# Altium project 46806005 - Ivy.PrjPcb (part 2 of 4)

## Sheet 800_Peripherals.SchDoc: Ivy - Verdin Industrial Board Rev 1.1
size Letter; Organization: Toradex Solutions Inc.; Address1: 6415 Northwest Drive; Address2: Mississauga, ON, L4V 1X1; Address3: Canada
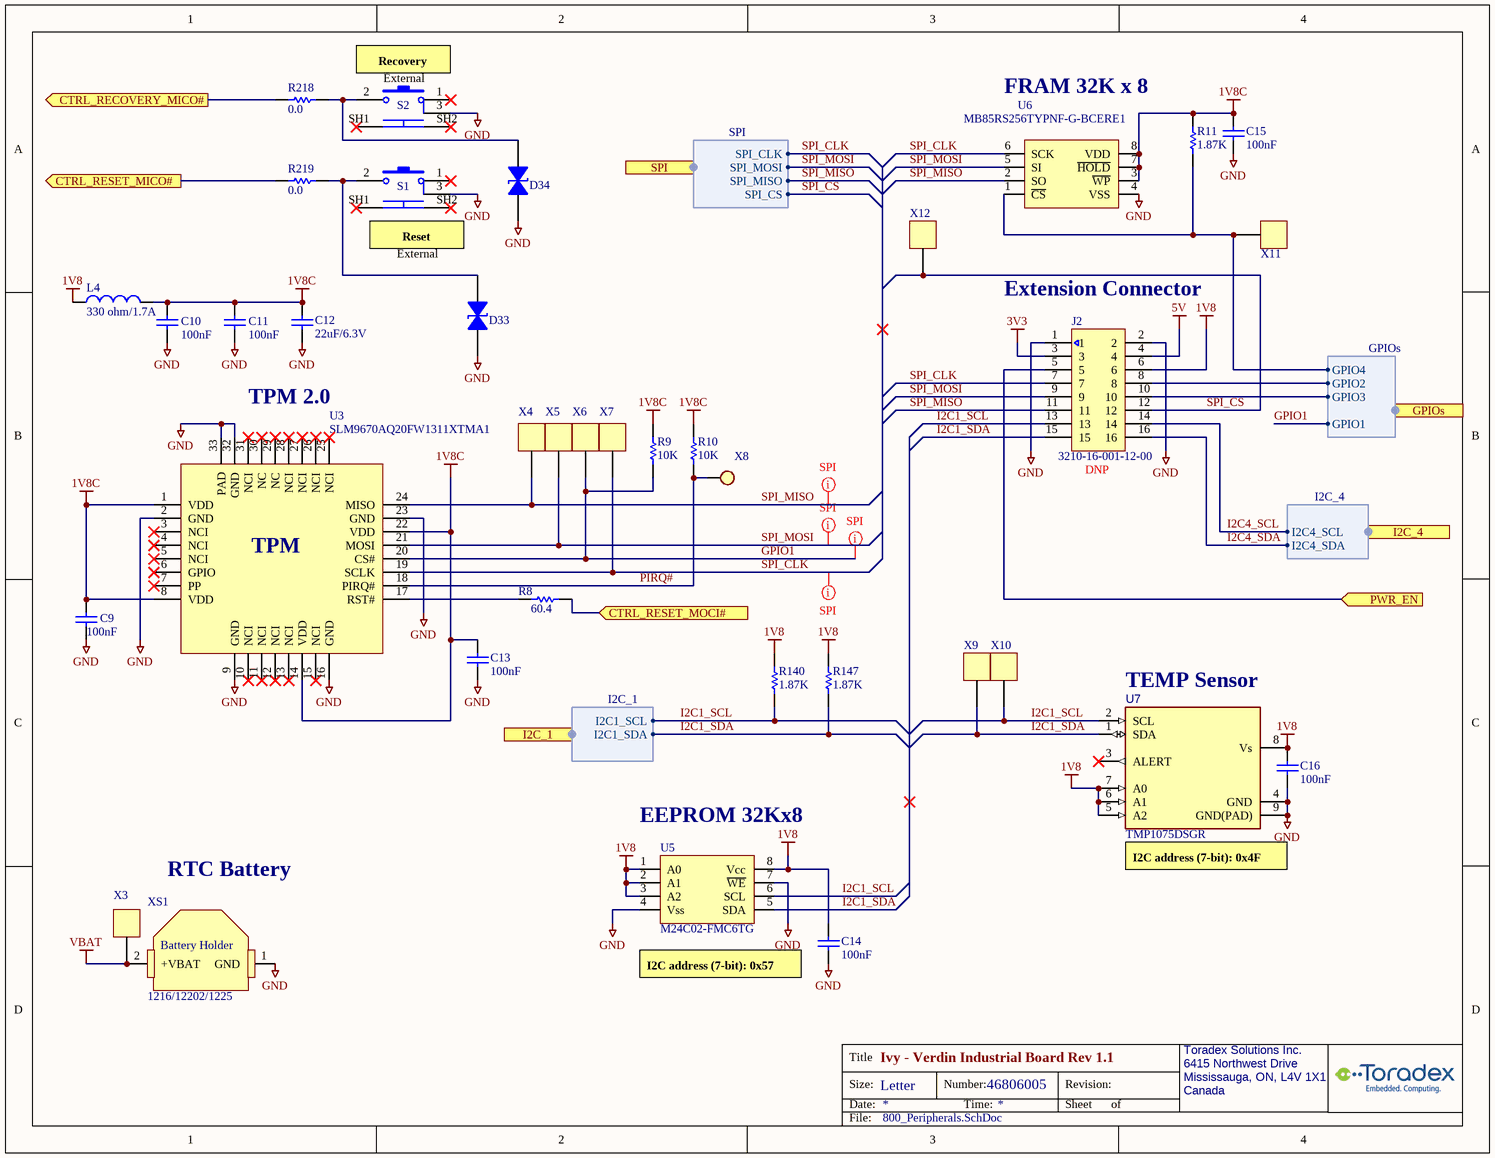
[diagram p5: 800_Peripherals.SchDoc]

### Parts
C9  100nF  [C0402_CAPC1005L]
C10  100nF  [C0402_CAPC1005L]
C11  100nF  [C0402_CAPC1005L]
C12  22uF/6.3V  [C0402_CAPC1005L]
C13  100nF  [C0402_CAPC1005L]
C14  100nF  [C0402_CAPC1005L]
C15  100nF  [C0402_CAPC1005L]
C16  100nF  [C0402_CAPC1005L]
D33  D5V0L1B2S9-7  [SOD923_DIO]  (value not drawn)
D34  D5V0L1B2S9-7  [SOD923_DIO]  (value not drawn)
J2  3210-16-001-12-00  [CNC_CONN16_3210-16-001-12-00]  (no BOM)
L4  value 330 ohm/1.7A  [INDC1608x095]  (hidden comment: 0405-Fer-0603-330ohm/1.7A)
R8  value 60.4  [R/0603]  (hidden comment: 2199-Res-0603-60.4)
R9  value 10K  [R0402_RESC1005L]  (hidden comment: 1572-Res-0402-10K)
R10  value 10K  [R0402_RESC1005L]  (hidden comment: 1572-Res-0402-10K)
R11  value 1.87K  [R0402_RESC1005L]  (hidden comment: 1536-Res-0402-1.87K)
R140  value 1.87K  [R0402_RESC1005L]  (hidden comment: 1536-Res-0402-1.87K)
R147  value 1.87K  [R0402_RESC1005L]  (hidden comment: 1536-Res-0402-1.87K)
R218  value 0.0  [R/0603]  (hidden comment: 0195-Res-0603-0.0ohm)
R219  value 0.0  [R/0603]  (hidden comment: 0195-Res-0603-0.0ohm)
S1  TL3340AF160QG  [SW_TL3340]  (value not drawn)
S2  TL3340AF160QG  [SW_TL3340]  (value not drawn)
U3  SLM9670AQ20FW1311XTMA1  [QFN50P500X500X90-33N-V]
U5  M24C02-FMC6TG  [M24C02FMC6TG]
U6  MB85RS256TYPNF-G-BCERE1  [SOIC-8]
U7  TMP1075DSGR  [WSON-8(2.1x2.1)_PAD]
X3  000-TestPoint  [TestPoint_1]  (value not drawn)
X4  000-TestPoint  [TestPoint_1]  (value not drawn)
X5  000-TestPoint  [TestPoint_1]  (value not drawn)
X6  000-TestPoint  [TestPoint_1]  (value not drawn)
X7  000-TestPoint  [TestPoint_1]  (value not drawn)
X8  000-TestPoint2  [TestPoint_3]  (value not drawn)
X9  000-TestPoint  [TestPoint_1]  (value not drawn)
X10  000-TestPoint  [TestPoint_1]  (value not drawn)
X11  000-TestPoint  [TestPoint_1]  (value not drawn)
X12  000-TestPoint  [TestPoint_1]  (value not drawn)
XS1  1216/12202/1225  [T_KEYSTONE_3000]

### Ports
CTRL_RECOVERY_MICO# (out), CTRL_RESET_MICO# (out), CTRL_RESET_MOCI# (in), GPIOs (harness GPIOs), I2C_1 (harness I2C_1), I2C_4 (harness I2C_4), PWR_EN (in), SPI (harness SPI)

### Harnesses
I2C_1: I2C1_SDA, I2C1_SCL
I2C_4: I2C4_SDA, I2C4_SCL
SPI: SPI_CLK, SPI_MISO, SPI_MOSI, SPI_CS
GPIOs: GPIO4, GPIO2, GPIO3, GPIO1

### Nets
1V8: C14.2 C16.2 J2.6 L4.2 R140.2 R147.2 U5.1(A0) U5.2(A1) U5.3(A2) U5.8(Vcc) U7.5(A2) U7.6(A1) U7.7(A0) U7.8(Vs)
1V8C: C9.2 C10.2 C11.2 C12.2 C13.2 C15.2 L4.1 R9.2 R10.2 R11.2 U3.1(VDD) U3.8(VDD) U3.14(VDD) U3.22(VDD) U6.3(~{WP}) U6.7(~{HOLD}) U6.8(VDD)
3V3: J2.3
5V: J2.4
GND: C9.1 C10.1 C11.1 C12.1 C13.1 C14.1 C15.1 C16.1 D33.1 D34.1 J2.1 J2.2 S1.3 S2.3 U3.2(GND) U3.9(GND) U3.16(GND) U3.23(GND) U3.32(GND) U3.33(PAD) U5.4(Vss) U5.7(~{WE}) U6.4(VSS) U7.4(GND) U7.9(GND(PAD)) XS1.1(GND)
VBAT: X3.1 XS1.2(+VBAT)
CTRL_RECOVERY_MICO#: R218.1 ; port CTRL_RECOVERY_MICO#
CTRL_RESET_MICO#: R219.1 ; port CTRL_RESET_MICO#
CTRL_RESET_MOCI#: R8.1 ; port CTRL_RESET_MOCI#
GPIO1: R9.1 U3.20(CS#) X6.1 ; port GPIOs.GPIO1
I2C1_SCL: J2.13 R140.1 U5.6(SCL) U7.2(SCL) X10.1 ; port I2C_1.I2C1_SCL
I2C1_SDA: J2.15 R147.1 U5.5(SDA) U7.1(SDA) X9.1 ; port I2C_1.I2C1_SDA
I2C4_SCL: J2.14 ; port I2C_4.I2C4_SCL
I2C4_SDA: J2.16 ; port I2C_4.I2C4_SDA
PIRQ#: R10.1 U3.18(PIRQ#) X8.1
PWR_EN: J2.5 ; port PWR_EN
SPI_CLK: J2.7 U3.19(SCLK) U6.6(SCK) X7.1 ; port SPI.SPI_CLK
SPI_CS: J2.12 X12.1 ; port SPI.SPI_CS
SPI_MISO: J2.11 U3.24(MISO) U6.2(SO) X4.1 ; port SPI.SPI_MISO
SPI_MOSI: J2.9 U3.21(MOSI) U6.5(SI) X5.1 ; port SPI.SPI_MOSI
NetD33_2: D33.2 R219.2 S1.2
NetD34_2: D34.2 R218.2 S2.2
NetJ2_8: J2.8 ; port GPIOs.GPIO2
NetJ2_10: J2.10 ; port GPIOs.GPIO3
NetM1_212: R11.1 U6.1(~{CS}) X11.1 ; port GPIOs.GPIO4
NetR8_2: R8.2 U3.17(RST#)

Not connected (* = marked no-connect by the designer): S1 1* SH1* SH2*; S2 1* SH1* SH2*; U3 3(NCI)* 4(NCI)* 5(NCI)* 6(GPIO)* 7(PP)* 10(NCI)* 11(NCI)* 12(NCI)* 13(NCI)* 15(NCI)* 25(NCI)* 26(NCI)* 27(NCI)* 28(NCI)* 29(NC)* 30(NC)* 31(NCI)*; U7 3(ALERT)*

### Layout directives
net class SPI: GPIO1, SPI_CLK, SPI_MISO, SPI_MOSI

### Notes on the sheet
- (near S2) Recovery
- (near S2) External
- FRAM 32K x 8
- (near S1) Reset
- External
- (near J2) Extension Connector
- TPM 2.0
- (near J2) DNP
- (near U7) TEMP Sensor
- (near U5) EEPROM 32Kx8
- RTC Battery
- (near U7) I2C address (7-bit): 0x4F
- I2C address (7-bit): 0x57

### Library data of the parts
C9-C11 C13-C16 = 1566-Cap-0402-100nF/50V: (-55 to 125 DegC AEC) Cap Ceramic 0.1uF 50V X7R 10% 0402; MfrNo: GRT155R71H104KE01D; Mfr: Murata; Alt: CL05B104KB54PNC,GCM155R71H104ME02D,GCM155R71H104KE02D,GCM155R71H104KE02J; PN: 1566
C12 = 2404-Cap-0402-22uF/6.3V: (-55 to 85 DegC) CAP CER 22UF 6.3V 20% X5R 0402; MfrNo: GRM155R60J226ME11D; Mfr: Murata; PN: 2404
D33 D34 = 1655-D5V0L1B2S9-7: (-65 to 155 DegC) TVS DIODE Vwm:5V Vcl:14V@6A SOD-923; Mfr: Diodes; PN: 1655
J2 = 2240-CONN-HDR 8x2 16POS 1.27MM: (-40 to 105 DegC) CONN HEADER VERT 8x2 16POS Shroud Latch Lock/Eject Hooks, Short 1.27MM SMT; Mfr: CNC Tech; PN: 2240
L4 = 0405-Fer-0603-330ohm/1.7A: (-55 to 125 DegC) FERRITE BEAD 330 OHM 0603 1.7A 80mohm, typ 48mohm; Mfr: TDK Corporation; MfrNo: MPZ1608S331ATA00; PN: 405; TR: 445-5221-2-ND; DR: 445-5221-6-ND; DR2: 810-MPZ1608S331ATA00
R8 = 2199-Res-0603-60.4: (-55 to 155 DegC) RES SMD 60.4 OHM 1% 1/10W 0603; MfrNo: CR0603-FX-60R4ELF; Mfr: Bourns; PN: 2199; Desc: (-55 to 155 DegC) RES SMD 60.4k OHM 1% 1/10W 0603
R9 R10 = 1572-Res-0402-10K: (-55 to 155 DegC AEC) RES 10K OHM 1% 1/16W 100ppm 0402; Mfr: Stackpole Electronics; MfrNo: RMCF0402FT10K0; Alt: AC0402FR-0710KL,AC0402FR-1310KL,CRGCQ0402F10K; PN: 1572
R11 R140 R147 = 1536-Res-0402-1.87K: (-55 to 155 DegC AEC) RES 1.87K OHM 1% 1/16W 100ppm 0402; MfrNo: RMCF0402FT1K87; Mfr: Stackpole Electronics; Alt: AC0402FR-071K87L,RK73H1ETTP1871F,ERJ-2RKF1871X; PN: 1536
R218 R219 = 0195-Res-0603-0.0ohm: RES 0.0 OHM 1/10W JUMP 0603; Mfr: Samsung; MfrNo: RC1608J000CS; PN: 195; Alt: 311-0.0GRCT-ND; Alt2: A106051CT-ND; TR: 1276-3510-2-ND
S1 S2 = 1659-Push Button: (-35 to 85 DegC) SWITCH TACTILE SPST-NO 0.05A 12V PushButton; Mfr: E-Switch; PN: 1659
U3 = 1361-SLM9670: (-40 to 105 DegC) IC Trusted Platform TPM SECURITY 32-VFQFN; Mfr: Infineon; PN: 1361
U5 = 1679-M24C02-FMC6TG: (-40 to 85 DegC) IC EEPROM 2KBIT (256B) 400KHZ 1.7-5.5V adr 0x50-57 2x3mm 8-UFDFN; Mfr: STMicroelectronics; PN: 1679
U6 = 1877-MB85RS256TY: (-40 to 125 DegC) IC FRAM Memory 1.8-3.6V 256Kbit 32x8KB SPI 33 MHz 8-SOIC; Mfr: Fujitsu; PN: 1877; Alt: MB85RS256TYPNF-G-AWERE2, MB85RS256TYPNF-GS-BCERE1
U7 = 1853-TMP1075DSGR: (-55 to 125 DegC) IC Temp Sensor I2C 1.7-5.5V WSON8; Mfr: Texas Instruments; PN: 1853
X3-X7 X9-X12 = 000-TestPoint: Note: this is PCB footprint only, no parts to buy or assemble
X8 = 000-TestPoint2: TestPoint SMD; Note: PCB footprint only, no parts to buy or assemble
XS1 = 1028-Conn-BatHolder-1220: (-40 to 105 DegC) Battery Holder Coin 12mm SMD 1216/1220/1225; MfrNo: 3000; Mfr: Keystone Electronics; PN: 1028

## Sheet 240_Translators.SchDoc: Ivy - Verdin Industrial Board Rev 1.1
size Letter; Organization: Toradex Solutions Inc.; Address1: 6415 Northwest Drive; Address2: Mississauga, ON, L4V 1X1; Address3: Canada
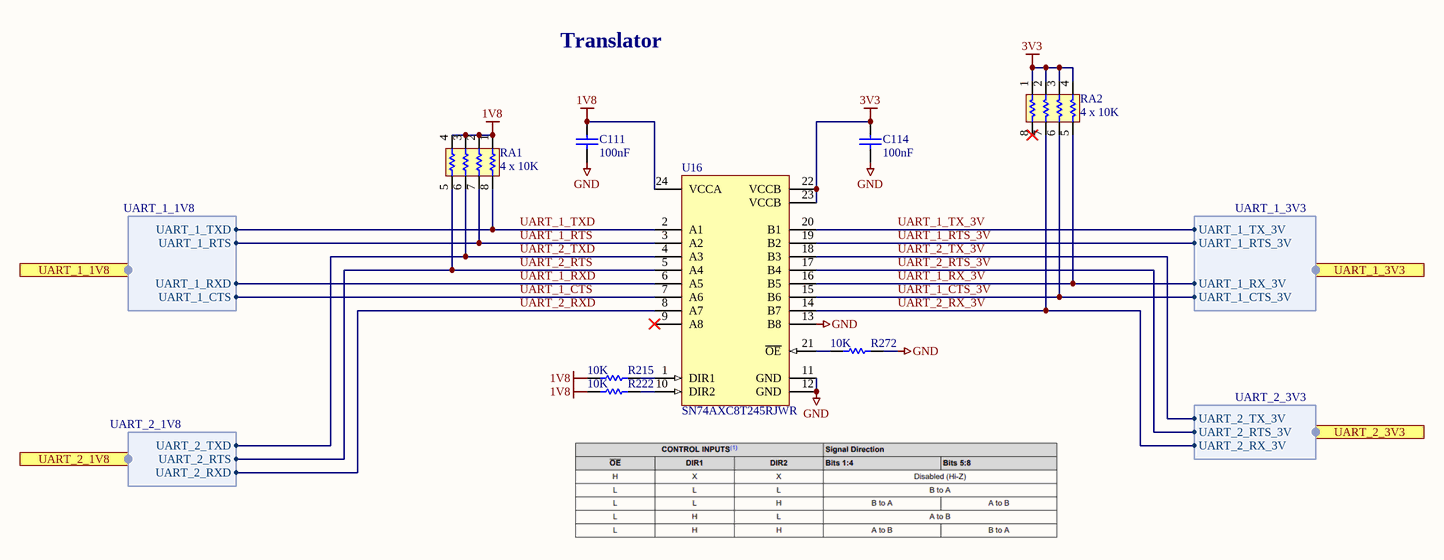
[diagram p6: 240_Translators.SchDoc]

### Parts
C111  100nF  [C0402_CAPC1005L]
C114  100nF  [C0402_CAPC1005L]
R215  value 10K  [R0402_RESC1005L]  (hidden comment: 1572-Res-0402-10K)
R222  value 10K  [R0402_RESC1005L]  (hidden comment: 1572-Res-0402-10K)
R272  value 10K  [R0402_RESC1005L]  (hidden comment: 1572-Res-0402-10K)
RA1  value 4 x 10K  [RESNET-1206-4]  (hidden comment: 1407-ResArr-1206-10K)
RA2  value 4 x 10K  [RESNET-1206-4]  (hidden comment: 1407-ResArr-1206-10K)
U16  SN74AXC8T245RJWR  [UQFN-24]

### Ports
UART_1_1V8 (harness UART_1_1V8), UART_1_3V3 (harness UART_1_3V3), UART_2_1V8 (harness UART_2_1V8), UART_2_3V3 (harness UART_2_3V3)

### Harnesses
UART_1_1V8: UART_1_RXD, UART_1_TXD, UART_1_RTS, UART_1_CTS
UART_2_1V8: UART_2_RXD, UART_2_TXD, UART_2_RTS
UART_2_3V3: UART_2_RX_3V, UART_2_TX_3V, UART_2_RTS_3V
UART_1_3V3: UART_1_RX_3V, UART_1_TX_3V, UART_1_RTS_3V, UART_1_CTS_3V

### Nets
1V8: C111.2 R215.1 R222.1 RA1.1 RA1.2 RA1.3 RA1.4 U16.24(VCCA)
3V3: C114.2 RA2.1 RA2.2 RA2.3 RA2.4 U16.22(VCCB) U16.23(VCCB)
GND: C111.1 C114.1 R272.2 U16.11(GND) U16.12(GND) U16.13(B8)
UART_1_CTS: U16.7(A6) ; port UART_1_1V8.UART_1_CTS
UART_1_CTS_3V: RA2.6 U16.15(B6) ; port UART_1_3V3.UART_1_CTS_3V
UART_1_RTS: RA1.7 U16.3(A2) ; port UART_1_1V8.UART_1_RTS
UART_1_RTS_3V: U16.19(B2) ; port UART_1_3V3.UART_1_RTS_3V
UART_1_RX_3V: RA2.5 U16.16(B5) ; port UART_1_3V3.UART_1_RX_3V
UART_1_RXD: U16.6(A5) ; port UART_1_1V8.UART_1_RXD
UART_1_TX_3V: U16.20(B1) ; port UART_1_3V3.UART_1_TX_3V
UART_1_TXD: RA1.8 U16.2(A1) ; port UART_1_1V8.UART_1_TXD
UART_2_RTS: RA1.5 U16.5(A4) ; port UART_2_1V8.UART_2_RTS
UART_2_RTS_3V: U16.17(B4) ; port UART_2_3V3.UART_2_RTS_3V
UART_2_RX_3V: RA2.7 U16.14(B7) ; port UART_2_3V3.UART_2_RX_3V
UART_2_RXD: U16.8(A7) ; port UART_2_1V8.UART_2_RXD
UART_2_TX_3V: U16.18(B3) ; port UART_2_3V3.UART_2_TX_3V
UART_2_TXD: RA1.6 U16.4(A3) ; port UART_2_1V8.UART_2_TXD
NetR215_2: R215.2 U16.1(DIR1)
NetR222_2: R222.2 U16.10(DIR2)
NetR272_1: R272.1 U16.21(~{OE})

Not connected (* = marked no-connect by the designer): RA2 8*; U16 9(A8)*

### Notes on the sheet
- Translator

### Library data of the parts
C111 C114 = 1566-Cap-0402-100nF/50V: as C9-C11 on sheet 800_Peripherals
R215 R222 R272 = 1572-Res-0402-10K: as R9 on sheet 800_Peripherals
RA1 RA2 = 1407-ResArr-1206-10K: (-55 to 125 DegC) RES ARRAY 4 RES 10K 1% 200ppm 1206; Mfr: Yageo; MfrNo: TC164-FR-0710KL; PN: 1407; Alt: YC164-FR-0710KL
U16 = 2540-SN74AXC8T245RJWR: (-40 to 125 DegC) IC TRANSLATION TXRX 0.65-3.6V 24UQFN; Mfr: Texas Instruments; PN: 2540

## Sheet 900_LTE.SchDoc: Ivy - Verdin Industrial Board Rev 1.1
size Letter; Organization: Toradex Solutions Inc.; Address1: 6415 Northwest Drive; Address2: Mississauga, ON, L4V 1X1; Address3: Canada
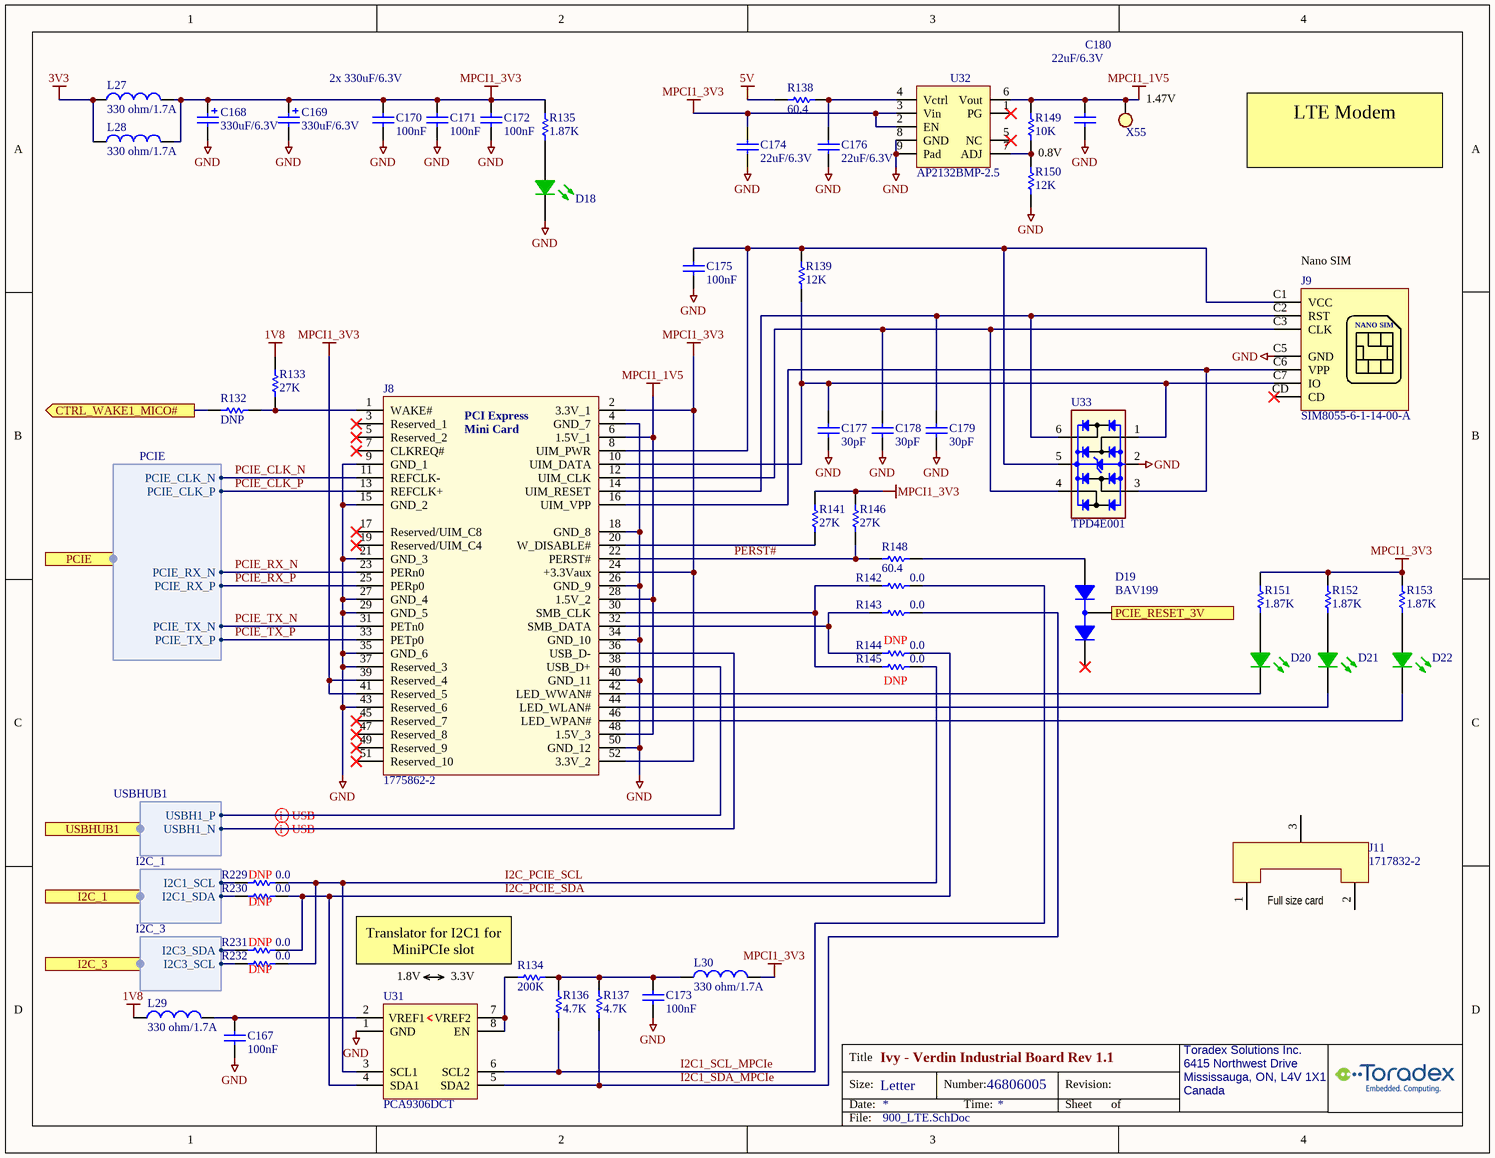
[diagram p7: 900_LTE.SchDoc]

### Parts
C167  100nF  [C0402_CAPC1005L]
C168  330uF/6.3V  [CAN-SMD-D630]
C169  330uF/6.3V  [CAN-SMD-D630]
C170  100nF  [C0402_CAPC1005L]
C171  100nF  [C0402_CAPC1005L]
C172  100nF  [C0402_CAPC1005L]
C173  100nF  [C0402_CAPC1005L]
C174  22uF/6.3V  [C0402_CAPC1005L]
C175  100nF  [C0402_CAPC1005L]
C176  22uF/6.3V  [C0402_CAPC1005L]
C177  value 30pF  [C/0603]  (hidden comment: 0958-Cap-0603-30pF/50V)
C178  value 30pF  [C/0603]  (hidden comment: 0958-Cap-0603-30pF/50V)
C179  value 30pF  [C/0603]  (hidden comment: 0958-Cap-0603-30pF/50V)
C180  22uF/6.3V  [C0402_CAPC1005L]
D18  Status  [LED-SMT-0603_APT1608CGCK]  (value not drawn)
D19  BAV199  [SOT23_M]
D20  Status  [LED-SMT-0603_APT1608CGCK]  (value not drawn)
D21  Status  [LED-SMT-0603_APT1608CGCK]  (value not drawn)
D22  Status  [LED-SMT-0603_APT1608CGCK]  (value not drawn)
J8  1775862-2  [17758622_FULL_SIZE]
J9  SIM8055-6-1-14-00-A  [SIM8055611400A]
J11  1717832-2  [MINI_PCIE_52PIN_CARD_LATCH_ALT]
L27  value 330 ohm/1.7A  [INDC1608x095]  (hidden comment: 0405-Fer-0603-330ohm/1.7A)
L28  value 330 ohm/1.7A  [INDC1608x095]  (hidden comment: 0405-Fer-0603-330ohm/1.7A)
L29  value 330 ohm/1.7A  [INDC1608x095]  (hidden comment: 0405-Fer-0603-330ohm/1.7A)
L30  value 330 ohm/1.7A  [INDC1608x095]  (hidden comment: 0405-Fer-0603-330ohm/1.7A)
R132  value DNP  [R/0603]  (hidden comment: 0000-Res-0603-DNP)
R133  value 27K  [R0402_RESC1005L]  (hidden comment: 1538-Res-0402-27k)
R134  value 200K  [R/0603]  (hidden comment: 1367-Res-0603-200K)
R135  value 1.87K  [R0402_RESC1005L]  (hidden comment: 1536-Res-0402-1.87K)
R136  value 4.7K  [R0402_RESC1005L]  (hidden comment: 2233-Res-0402-4.7K)
R137  value 4.7K  [R0402_RESC1005L]  (hidden comment: 2233-Res-0402-4.7K)
R138  value 60.4  [R/0603]  (hidden comment: 2199-Res-0603-60.4)
R139  value 12K  [R0402_RESC1005L]  (hidden comment: 1537-Res-0402-12K)
R141  value 27K  [R0402_RESC1005L]  (hidden comment: 1538-Res-0402-27k)
R142  value 0.0  [R/0603]  (hidden comment: 0195-Res-0603-0.0ohm)
R143  value 0.0  [R/0603]  (hidden comment: 0195-Res-0603-0.0ohm)
R144  value 0.0  [R/0603]  (hidden comment: 0195-Res-0603-0.0ohm)  (no BOM)
R145  value 0.0  [R/0603]  (hidden comment: 0195-Res-0603-0.0ohm)  (no BOM)
R146  value 27K  [R0402_RESC1005L]  (hidden comment: 1538-Res-0402-27k)
R148  value 60.4  [R/0603]  (hidden comment: 2199-Res-0603-60.4)
R149  value 10K  [R0402_RESC1005L]  (hidden comment: 1572-Res-0402-10K)
R150  value 12K  [R0402_RESC1005L]  (hidden comment: 1537-Res-0402-12K)
R151  value 1.87K  [R0402_RESC1005L]  (hidden comment: 1536-Res-0402-1.87K)
R152  value 1.87K  [R0402_RESC1005L]  (hidden comment: 1536-Res-0402-1.87K)
R153  value 1.87K  [R0402_RESC1005L]  (hidden comment: 1536-Res-0402-1.87K)
R229  value 0.0  [R/0603]  (hidden comment: 0195-Res-0603-0.0ohm)  (no BOM)
R230  value 0.0  [R/0603]  (hidden comment: 0195-Res-0603-0.0ohm)  (no BOM)
R231  value 0.0  [R/0603]  (hidden comment: 0195-Res-0603-0.0ohm)  (no BOM)
R232  value 0.0  [R/0603]  (hidden comment: 0195-Res-0603-0.0ohm)  (no BOM)
U31  PCA9306DCT  [TSSO3x5-G8/X.35]
U32  AP2132BMP-2.5  [SOP-9 TP_ALT]
U33  TPD4E001  [SOT23-6]
X55  000-TestPoint2  [TestPoint_3]  (value not drawn)

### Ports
CTRL_WAKE1_MICO# (out), I2C_1 (harness I2C_1), I2C_3 (harness I2C_3), PCIE (harness PCIe), PCIE_RESET_3V (in), USBHUB1 (harness USBHUB1)

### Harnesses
PCIE: PCIE_CLK_N, PCIE_CLK_P, PCIE_RX_N, PCIE_RX_P, PCIE_TX_N, PCIE_TX_P
USBHUB1: USBH1_N, USBH1_P
I2C_1: I2C1_SDA, I2C1_SCL
I2C_3: I2C3_SDA, I2C3_SCL

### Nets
1V8: L29.1 R133.1
3V3: L27.1 L28.1
5V: R138.2
GND: C167.1 C168.2 C169.2 C170.1 C171.1 C172.1 C173.1 C174.1 C175.1 C176.1 C177.1 C178.1 C179.1 C180.1 D18.2(K) J8.4(GND_7) J8.9(GND_1) J8.15(GND_2) J8.18(GND_8) J8.21(GND_3) J8.26(GND_9) J8.27(GND_4) J8.29(GND_5) J8.34(GND_10) J8.35(GND_6) J8.37(Reserved_3) J8.40(GND_11) J8.43(Reserved_6) J8.50(GND_12) J9.C5(GND) R150.1 U31.1(GND) U32.8(GND) U32.9(Pad) U33.2
MPCI1_1V5: C180.2 J8.6(1.5V_1) J8.28(1.5V_2) J8.48(1.5V_3) R149.2 U32.6(Vout) X55.1
MPCI1_3V3: C168.1 C169.1 C170.2 C171.2 C172.2 C174.2 J8.2(3.3V_1) J8.24(+3.3Vaux) J8.39(Reserved_4) J8.41(Reserved_5) J8.52(3.3V_2) L27.2 L28.2 L30.2 R135.2 R141.1 R146.1 R151.2 R152.2 R153.2 U32.2(EN) U32.3(Vin)
CTRL_WAKE1_MICO#: R132.1 ; port CTRL_WAKE1_MICO#
I2C1_SCL: R229.2 ; port I2C_1.I2C1_SCL
I2C1_SCL_MPCIe: R136.1 R142.1 U31.6(SCL2)
I2C1_SDA: R230.2 ; port I2C_1.I2C1_SDA
I2C1_SDA_MPCIe: R137.1 R143.1 U31.5(SDA2)
I2C_PCIE_SCL: R145.1 R229.1 R232.1 U31.3(SCL1)
I2C_PCIE_SDA: R144.1 R230.1 R231.1 U31.4(SDA1)
PCIE_CLK_N: J8.11(REFCLK-) ; port PCIE.PCIE_CLK_N
PCIE_CLK_P: J8.13(REFCLK+) ; port PCIE.PCIE_CLK_P
PCIE_RESET_3V: D19.3(K1/A2) ; port PCIE_RESET_3V
PCIE_RX_N: J8.23(PERn0) ; port PCIE.PCIE_RX_N
PCIE_RX_P: J8.25(PERp0) ; port PCIE.PCIE_RX_P
PCIE_TX_N: J8.31(PETn0) ; port PCIE.PCIE_TX_N
PCIE_TX_P: J8.33(PETp0) ; port PCIE.PCIE_TX_P
PERST#: J8.22(PERST#) R146.2 R148.2
NetC167_2: C167.2 L29.2 U31.2(VREF1)
NetC173_2: C173.2 L30.1 R134.1 R136.2 R137.2
NetC175_2: C175.2 J8.8(UIM_PWR) J9.C1(VCC) R139.2 U33.5
NetC176_2: C176.2 R138.1 U32.4(Vctrl)
NetC177_2: C177.2 J8.10(UIM_DATA) J9.C7(IO) R139.1 U33.1
NetC178_2: C178.2 J8.12(UIM_CLK) J9.C3(CLK) U33.4
NetC179_2: C179.2 J8.14(UIM_RESET) J9.C2(RST) U33.6
NetD18_1: D18.1(A) R135.1
NetD19_1: D19.1(A1) R148.1
NetD20_1: D20.1(A) R151.1
NetD20_2: D20.2(K) J8.42(LED_WWAN#)
NetD21_1: D21.1(A) R152.1
NetD21_2: D21.2(K) J8.44(LED_WLAN#)
NetD22_1: D22.1(A) R153.1
NetD22_2: D22.2(K) J8.46(LED_WPAN#)
NetJ8_1: J8.1(WAKE#) R132.2 R133.2
NetJ8_16: J8.16(UIM_VPP) J9.C6(VPP) U33.3
NetJ8_20: J8.20(W_DISABLE#) R141.2
NetJ8_30: J8.30(SMB_CLK) R142.2 R145.2
NetJ8_32: J8.32(SMB_DATA) R143.2 R144.2
NetJ8_36: J8.36(USB_D-) ; port USBHUB1.USBH1_N
NetJ8_38: J8.38(USB_D+) ; port USBHUB1.USBH1_P
NetM1_57: R231.2 ; port I2C_3.I2C3_SDA
NetM1_59: R232.2 ; port I2C_3.I2C3_SCL
NetR134_2: R134.2 U31.7(VREF2) U31.8(EN)
NetR149_1: R149.1 R150.2 U32.7(ADJ)

Not connected (* = marked no-connect by the designer): D19 2(K2)*; J8 3(Reserved_1)* 5(Reserved_2)* 7(CLKREQ#)* 17(Reserved/UIM_C8)* 19(Reserved/UIM_C4)* 45(Reserved_7)* 47(Reserved_8)* 49(Reserved_9)* 51(Reserved_10)*; J9 CD*; J11 1 2 3; U32 1(PG)* 5(NC)*

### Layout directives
differential pair; differential pair class USBH1; differential pair class USB: NetJ8_36, NetJ8_38

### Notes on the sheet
- 2x 330uF/6.3V
- (near X55) 1.47V
- 0.8V
- LTE Modem
- (near J9) Nano SIM
- (near R144) DNP
- (near R145) DNP
- (near R229) DNP
- (near R230) DNP
- (near J11) Full size card
- (near R231) DNP
- (near R232) DNP
- (near R134) Translator for I2C1 for MiniPCIe slot
- (near U31) 1.8V
- 3.3V

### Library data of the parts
C167 C170-C173 C175 = 1566-Cap-0402-100nF/50V: as C9-C11 on sheet 800_Peripherals
C168 C169 = 2241-Cap-6.6x6.6-330uF/6.3V: (-55 to 105 DegC) CAP ALUM POLY 33UF 6.3V 20% SMD 10mohm 6.6x6.6x6.1mm Ir:3.9A (100kHz); Mfr: United Chemi-Con; MfrNo: APXF6R3ARA331MF61G; PN: 2241
C174 C176 C180 = 2404-Cap-0402-22uF/6.3V: as C12 on sheet 800_Peripherals
C177-C179 = 0958-Cap-0603-30pF/50V: (-55 - 125 DegC) CAP CER 30PF 50V C0G/NP0 0603; Mfr: Kyocera AVX; MfrNo: 06035A300JAT2A\4K; PN: 958; Alt: CC0603GRNPO9BN300,06031A300J4T2A
D18 D20-D22 = 0333-LED Green 0603: (-40 to 85 DegC) LED GREEN 0603 50mcd; MfrNo: APT1608CGCK; Mfr: Kingbright; Alt: 754-1357-1-ND; Alt2: 160-1834-1-ND; PN: 333; DR: 754-1116-6-ND; DR2: 604-APT1608CGCK
D19 = 0859-BAV199: (-65 to 150 DegC) DIODE ARRAY SeriesConnection 85V 140MA SOT23-3 Low Leakage Ilk=5nA; MfrNo: BAV199-7-F; Mfr: Diodes Incorporated; Alt: BAV199E6433HTMA1,BAV199HMT116,BAV199,235; PN: 859
J8 = 1390-Conn-MiniPCIe: (-55 to 85 DegC) CONN MINI EXPRESS CARD 52POS SMD; Mfr: TE Connectivity; PN: 1390
J9 = 1401-Conn-NanoSIM: (-40 to 85 DegC) CONN SIM NANO PUSH PULL 6P, 1.35mm height; Mfr: Global Connector Technology; PN: 1401
J11 = 1391-Conn-MiniPCIe-Latch: (-55 to 85 DegC) CONN MINI EXPRESS CARD LATCH SMD; Mfr: TE Connectivity; PN: 1391; Note: Latch for PN 25001390
L27-L30 = 0405-Fer-0603-330ohm/1.7A: as L4 on sheet 800_Peripherals
R132 = 0000-Res-0603-DNP: RES 0603
R133 R141 R146 = 1538-Res-0402-27k: (-55 to 155 DegC AEC) RES 27K OHM 1% 1/16W 100ppm 0402; Mfr: Stackpole Electronics; MfrNo: RMCF0402FT27K0; PN: 1538; Alt: AC0402FR-0727KL,CRGCQ0402F27K
R134 = 1367-Res-0603-200K: (-55 to 155 DegC) RES SMD 200K 1% 1/10W 0603 100ppm; Mfr: Stackpole Electronics; MfrNo: RMCF0603FT200K; Alt: CR0603-FX-2003ELF,RC0603FR-07200KL,RK73H1JTTD2003F; PN: 1367
R135 R151-R153 = 1536-Res-0402-1.87K: as R11 on sheet 800_Peripherals
R136 R137 = 2233-Res-0402-4.7K: (-55 to 155 DegC) RES 4.70K OHM 1/16W 1% 0402 100ppm; MfrNo: RC0402FR-074K7L; Mfr: Yageo; PN: 2233
R138 R148 = 2199-Res-0603-60.4: as R8 on sheet 800_Peripherals
R139 R150 = 1537-Res-0402-12K: (-55 to 155 DegC AEC) RES 12K OHM 1% 1/16W 100ppm 0402; Mfr: Stackpole Electronics; MfrNo: RMCF0402FT12K0; PN: 1537; Alt: AC0402FR-0712KL,CRGCQ0402F12K
R142-R145 R229-R232 = 0195-Res-0603-0.0ohm: RES 0.0 OHM 1/10W JUMP 0603; Mfr: Samsung; MfrNo: RC1608J000CS; Alt: 311-0.0GRCT-ND; Alt2: A106051CT-ND; PN: 195; TR: 1276-3510-2-ND
R149 = 1572-Res-0402-10K: (-55 to 155 DegC AEC) RES 10K OHM 1% 1/16W 100ppm 0402; Mfr: Stackpole Electronics; MfrNo: RMCF0402FT10K0; PN: 1572; Alt: AC0402FR-0710KL,AC0402FR-1310KL,CRGCQ0402F10K
U31 = 0972-PCA9306DCT: (-40 to 85 DegC) IC TRANSLTR BIDIRECTIONAL I2C SM8; MfrNo: PCA9306DCTR; Mfr: Texas Instruments; PN: 972
U32 = 1467-AP2132BMP-2.5: (-40 to 85 DegC) IC REG LDO LINEAR POS ADJ 5V 2A 8SO; MfrNo: AP2132BMP-2.5TRG1; Mfr: Diodes; PN: 1467; Desc: (-40 to 85 DegC) IC REG BUCK ADJ Sync 5A Vin:3.8 to 40V 100-2200kHz FSS (spread spectrum) MaxDuty:100% SO-8EP; Note: These can be also used with adjust Voltage circuit: AP2132BMP-1.2TRG1, AP2132BMP-1.5TRG1
U33 = 0740-TPD4E001: (-40 to 125 DegC AEC) TVS DIODE 5.5VWM 16VC SOT-23-6; MfrNo: TPD4E001QDBVRQ1; Mfr: Texas Instruments; PN: 740; Alt: TPD4E001DBVR
X55 = 000-TestPoint2: as X8 on sheet 800_Peripherals

## Sheet 300_CAN_Transceivers.SchDoc: Ivy - Verdin Industrial Board Rev 1.1
size Letter; Organization: Toradex Solutions Inc.; Address1: 6415 Northwest Drive; Address2: Mississauga, ON, L4V 1X1; Address3: Canada
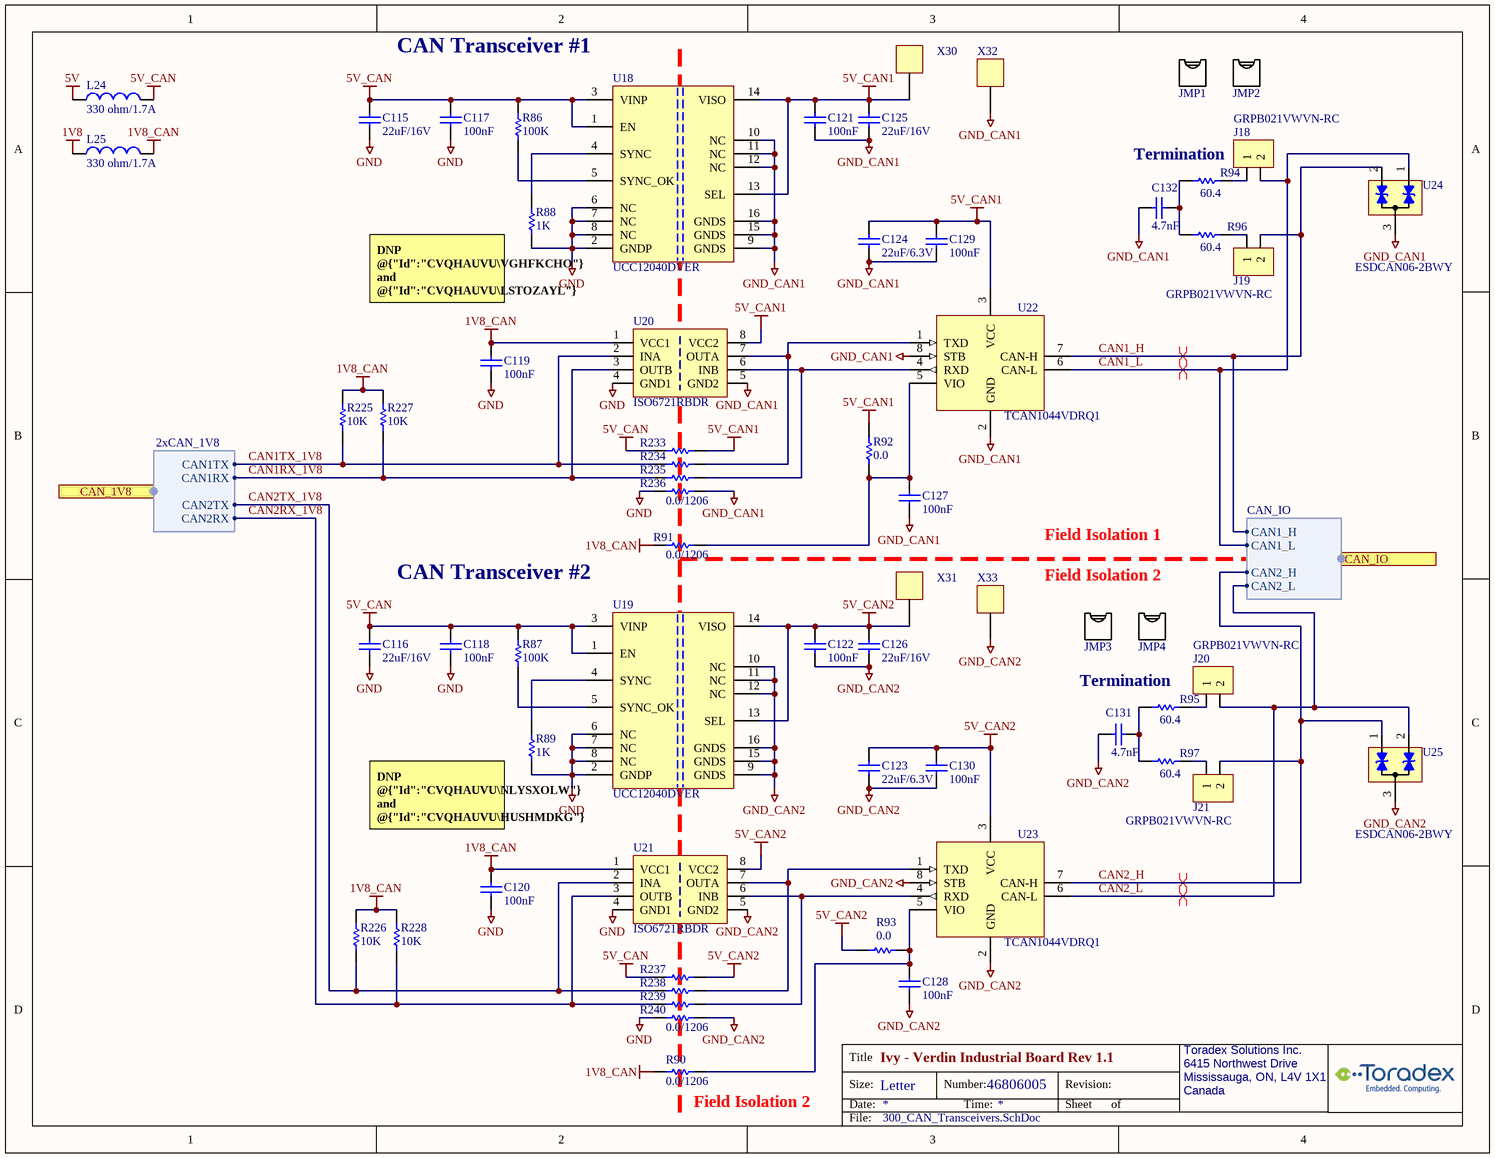
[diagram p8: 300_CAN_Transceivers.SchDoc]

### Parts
C115  value 22uF/16V  [C/0805]  (hidden comment: 1314-Cap-0805-22uF/16V)
C116  value 22uF/16V  [C/0805]  (hidden comment: 1314-Cap-0805-22uF/16V)
C117  100nF  [C0402_CAPC1005L]
C118  100nF  [C0402_CAPC1005L]
C119  100nF  [C0402_CAPC1005L]
C120  100nF  [C0402_CAPC1005L]
C121  100nF  [C0402_CAPC1005L]
C122  100nF  [C0402_CAPC1005L]
C123  22uF/6.3V  [C0402_CAPC1005L]
C124  22uF/6.3V  [C0402_CAPC1005L]
C125  value 22uF/16V  [C/0805]  (hidden comment: 1314-Cap-0805-22uF/16V)
C126  value 22uF/16V  [C/0805]  (hidden comment: 1314-Cap-0805-22uF/16V)
C127  100nF  [C0402_CAPC1005L]
C128  100nF  [C0402_CAPC1005L]
C129  100nF  [C0402_CAPC1005L]
C130  100nF  [C0402_CAPC1005L]
C131  value 4.7nF  [C/0603]  (hidden comment: 0346-Cap-0603-4.7nF)
C132  value 4.7nF  [C/0603]  (hidden comment: 0346-Cap-0603-4.7nF)
J18  GRPB021VWVN-RC  [CONN_WVN-RC_SUL]
J19  GRPB021VWVN-RC  [CONN_WVN-RC_SUL]
J20  GRPB021VWVN-RC  [CONN_WVN-RC_SUL]
J21  GRPB021VWVN-RC  [CONN_WVN-RC_SUL]
JMP1  Shunt Jumper  (value not drawn)  (mechanical)
JMP2  Shunt Jumper  (value not drawn)  (mechanical)
JMP3  Shunt Jumper  (value not drawn)  (mechanical)
JMP4  Shunt Jumper  (value not drawn)  (mechanical)
L24  value 330 ohm/1.7A  [INDC1608x095]  (hidden comment: 0405-Fer-0603-330ohm/1.7A)
L25  value 330 ohm/1.7A  [INDC1608x095]  (hidden comment: 0405-Fer-0603-330ohm/1.7A)
R86  value 100K  [R0402_RESC1005L]  (hidden comment: 1977-Res-0402-100K)
R87  value 100K  [R0402_RESC1005L]  (hidden comment: 1977-Res-0402-100K)
R88  value 1K  [R0402_RESC1005L]  (hidden comment: 1650-Res-0402-1K)
R89  value 1K  [R0402_RESC1005L]  (hidden comment: 1650-Res-0402-1K)
R90  value 0.0/1206  [R/1206]  (hidden comment: 0038-Res-1206-0.0ohm)
R91  value 0.0/1206  [R/1206]  (hidden comment: 0038-Res-1206-0.0ohm)
R92  value 0.0  [R/0603]  (hidden comment: 0195-Res-0603-0.0ohm)
R93  value 0.0  [R/0603]  (hidden comment: 0195-Res-0603-0.0ohm)
R94  value 60.4  [R/0603]  (hidden comment: 2199-Res-0603-60.4)
R95  value 60.4  [R/0603]  (hidden comment: 2199-Res-0603-60.4)
R96  value 60.4  [R/0603]  (hidden comment: 2199-Res-0603-60.4)
R97  value 60.4  [R/0603]  (hidden comment: 2199-Res-0603-60.4)
R225  value 10K  [R0402_RESC1005L]  (hidden comment: 1572-Res-0402-10K)
R226  value 10K  [R0402_RESC1005L]  (hidden comment: 1572-Res-0402-10K)
R227  value 10K  [R0402_RESC1005L]  (hidden comment: 1572-Res-0402-10K)
R228  value 10K  [R0402_RESC1005L]  (hidden comment: 1572-Res-0402-10K)
R233  0038-Res-1206-0.0ohm  [R/1206]  (value not drawn)
R234  0038-Res-1206-0.0ohm  [R/1206]  (value not drawn)
R235  0038-Res-1206-0.0ohm  [R/1206]  (value not drawn)
R236  value 0.0/1206  [R/1206]  (hidden comment: 0038-Res-1206-0.0ohm)
R237  0038-Res-1206-0.0ohm  [R/1206]  (value not drawn)
R238  0038-Res-1206-0.0ohm  [R/1206]  (value not drawn)
R239  0038-Res-1206-0.0ohm  [R/1206]  (value not drawn)
R240  value 0.0/1206  [R/1206]  (hidden comment: 0038-Res-1206-0.0ohm)
U18  UCC12040DVER  [SOIC-16]
U19  UCC12040DVER  [SOIC-16]
U20  ISO6721RBDR  [SOIC-8]
U21  ISO6721RBDR  [SOIC-8]
U22  TCAN1044VDRQ1  [SOIC-8]
U23  TCAN1044VDRQ1  [SOIC-8]
U24  ESDCAN06-2BWY  [SOT-323]
U25  ESDCAN06-2BWY  [SOT-323]
X30  000-TestPoint  [TestPoint_1]  (value not drawn)
X31  000-TestPoint  [TestPoint_1]  (value not drawn)
X32  000-TestPoint  [TestPoint_1]  (value not drawn)
X33  000-TestPoint  [TestPoint_1]  (value not drawn)

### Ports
CAN_1V8 (harness 2xCAN_1V8), CAN_IO (harness CAN_IO)

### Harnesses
2xCAN_1V8: CAN1TX, CAN1RX, CAN2TX, CAN2RX
CAN_IO: CAN2_H, CAN2_L, CAN1_H, CAN1_L

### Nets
1V8: L25.1
1V8_CAN: C119.1 C120.1 L25.2 R90.1 R91.2 R225.1 R226.1 R227.1 R228.1 U20.1(VCC1) U21.1(VCC1)
5V: L24.1
5V_CAN: C115.2 C116.2 C117.1 C118.1 L24.2 R86.2 R87.2 R233.2 R237.1 U18.1(EN) U18.3(VINP) U19.1(EN) U19.3(VINP)
5V_CAN1: C121.1 C124.2 C125.2 C129.1 R92.2 R233.1 U18.13(SEL) U18.14(VISO) U20.8(VCC2) U22.3(VCC) X30.1
5V_CAN2: C122.1 C123.2 C126.2 C130.1 R93.2 R237.2 U19.13(SEL) U19.14(VISO) U21.8(VCC2) U23.3(VCC) X31.1
GND: C115.1 C116.1 C117.2 C118.2 C119.2 C120.2 R88.1 R89.1 R236.1 R240.1 U18.2(GNDP) U18.6(NC) U18.7(NC) U18.8(NC) U19.2(GNDP) U19.6(NC) U19.7(NC) U19.8(NC) U20.4(GND1) U21.4(GND1)
GND_CAN1: C121.2 C124.1 C125.1 C127.1 C129.2 C132.1 R236.2 U18.9(GNDS) U18.10(NC) U18.11(NC) U18.12(NC) U18.15(GNDS) U18.16(GNDS) U20.5(GND2) U22.2(GND) U22.8(STB) U24.3 X32.1
GND_CAN2: C122.2 C123.1 C126.1 C128.1 C130.2 C131.1 R240.2 U19.9(GNDS) U19.10(NC) U19.11(NC) U19.12(NC) U19.15(GNDS) U19.16(GNDS) U21.5(GND2) U23.2(GND) U23.8(STB) U25.3 X33.1
CAN1_H: J19.2 U22.7(CAN-H) U24.2 ; port CAN_IO.CAN1_H
CAN1_L: J18.2 U22.6(CAN-L) U24.1 ; port CAN_IO.CAN1_L
CAN1RX_1V8: R227.2 R235.1 U20.3(OUTB) ; port CAN_1V8.CAN1RX
CAN1TX_1V8: R225.2 R234.1 U20.2(INA) ; port CAN_1V8.CAN1TX
CAN2_H: J21.2 U23.7(CAN-H) U25.1 ; port CAN_IO.CAN2_H
CAN2_L: J20.2 U23.6(CAN-L) U25.2 ; port CAN_IO.CAN2_L
CAN2RX_1V8: R228.2 R239.1 U21.3(OUTB) ; port CAN_1V8.CAN2RX
CAN2TX_1V8: R226.2 R238.1 U21.2(INA) ; port CAN_1V8.CAN2TX
NetC127_2: C127.2 R91.1 R92.1 U22.5(VIO)
NetC128_2: C128.2 R90.2 R93.1 U23.5(VIO)
NetC131_2: C131.2 R95.1 R97.1
NetC132_2: C132.2 R94.1 R96.1
NetJ18_1: J18.1 R94.2
NetJ19_1: J19.1 R96.2
NetJ20_1: J20.1 R95.2
NetJ21_1: J21.1 R97.2
NetR86_1: R86.1 U18.5(SYNC_OK)
NetR87_1: R87.1 U19.5(SYNC_OK)
NetR88_2: R88.2 U18.4(SYNC)
NetR89_2: R89.2 U19.4(SYNC)
NetR234_2: R234.2 U20.7(OUTA) U22.1(TXD)
NetR235_2: R235.2 U20.6(INB) U22.4(RXD)
NetR238_2: R238.2 U21.7(OUTA) U23.1(TXD)
NetR239_2: R239.2 U21.6(INB) U23.4(RXD)

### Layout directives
differential pair; differential pair class CAN: CAN1_H, CAN1_L, CAN2_H, CAN2_L

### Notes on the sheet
- CAN Transceiver #1
- Termination
- (near R88) DNP @{"Id":"CVQHAUVU\VGHFKCHO"} and @{"Id":"CVQHAUVU\LSTOZAYL"} if @{"Id":"CVQHAUVU\EXQIJSEJ","ObjectType":2}, @{"Id":"CVQHAUVU\FPYPKWKA","ObjectType":2}, @{"Id":"CVQHAUVU\KOMEBSIN","ObjectType":2}, @{"Id":"CVQHAUVU\FIXPCWRI","ObjectType":2} and @{"Id":"CVQHAUVU\DUMHUNPN","ObjectType":2} are mounted.
- Field Isolation 1
- CAN Transceiver #2
- Field Isolation 2
- (near R95) Termination
- (near R89) DNP @{"Id":"CVQHAUVU\NLYSXOLW"} and @{"Id":"CVQHAUVU\HUSHMDKG"} if @{"Id":"CVQHAUVU\KSCWPYYC","ObjectType":2}, @{"Id":"CVQHAUVU\LTHGTOLS","ObjectType":2}, @{"Id":"CVQHAUVU\JVBMRTFO","ObjectType":2}, @{"Id":"CVQHAUVU\RWBWDMFZ","ObjectType":2} and @{"Id":"CVQHAUVU\PNPZHAQY","ObjectType":2} are mounted.
- (near R90) Field Isolation 2

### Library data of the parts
C115 C116 C125 C126 = 1314-Cap-0805-22uF/16V: (-55 to 85 DegC) CAP CER 22uF 16V X5R 0805; MfrNo: CL21A226MOQNNNE; Mfr: Samsung; PN: 1314; Alt: CL21A226MOCLRNC,CL21A226KOQNNNG,GRM21BR61C226ME44L,EMK212BBJ226MG-T
C117-C122 C129 C130 = 1566-Cap-0402-100nF/50V: as C9-C11 on sheet 800_Peripherals
C123 C124 = 2404-Cap-0402-22uF/6.3V: as C12 on sheet 800_Peripherals
C127 C128 = 1566-Cap-0402-100nF/50V: (-55 to 125 DegC AEC) Cap Ceramic 0.1uF 50V X7R 10% 0402; Mfr: Murata; MfrNo: GRT155R71H104KE01D; PN: 1566; Alt: CL05B104KB54PNC,GCM155R71H104ME02D,GCM155R71H104KE02D,GCM155R71H104KE02J
C131 C132 = 0346-Cap-0603-4.7nF: CAP CER 4700PF 50V 5% NP0 0603; MfrNo: GRM1885C1H472JA01D; Mfr: Murata Electronics North America; PN: 346; Alt: 445-13986-1-ND; Alt2: 445-6912-1-ND
J18-J21 = 2350-CONN HEADER VERT 2POS 1.27MM: (-40 to 105 DegC) CONN HEADER VERT 2POS 1.27MM GOLD; Mfr: Sullins; PN: 2350
JMP1-JMP4 = MECH-Shunt-Jumper-Black-2.54mm: Manufacturer Name: Assmann; Manufacturer Part No.: HMSC-G; PN: 20000617
L24 L25 = 0405-Fer-0603-330ohm/1.7A: as L4 on sheet 800_Peripherals
R86 R87 = 1977-Res-0402-100K: (-55 to 155 DegC) RES 100K OHM 1/16W 1% 0402 SMD; Mfr: Yageo; MfrNo: RC0402FR-07100KL; PN: 1977
R88 R89 = 1650-Res-0402-1K: (-55 to 155 DegC AEC) RES 1K OHM 1% 1/16W 100ppm 0402; Mfr: TE Connectivity; MfrNo: CRGCQ0402F1K0; PN: 1650; Alt: CR0402AFX-1001GLF,AC0402FR-131KL,AC0402FR-071KL
R90 R91 R233-R240 = 0038-Res-1206-0.0ohm: (-55 to 155 DegC) RES 0.0 OHM 1/4W JUMPER 1206; Mfr: TE; MfrNo: 1623693-1; PN: 38; Alt: 311-0.0ERCT-ND; Alt2: RMCF1206ZT0R00CT-ND
R92 R93 = 0195-Res-0603-0.0ohm: as R142 on sheet 900_LTE
R94-R97 = 2199-Res-0603-60.4: (-55 to 155 DegC) RES SMD 60.4 OHM 1% 1/10W 0603; Mfr: Bourns; MfrNo: CR0603-FX-60R4ELF; Desc: (-55 to 155 DegC) RES SMD 60.4k OHM 1% 1/10W 0603; PN: 2199
R225-R228 = 1572-Res-0402-10K: as R9 on sheet 800_Peripherals
U18 U19 = 2065-UCC12040DVER: (-40 to 125 DegC) IC Isolated DC DC Converter-Output 3.3V, 5V 140mA, 4.5V-5.5V Input; Mfr: Texas Instruments; PN: 2065
U20 U21 = 2198-ISO6721RBDR: (-40 to 125 DegC) IC DGTL ISO GENERAL-PURPOSE, DUAL-CHANNEL, 1x In, 1x Out 1.71-5.5V; Mfr: Texas Instruments; PN: 2198
U22 U23 = 1620-TCAN1044VDRQ1: (-40 to 125 DegC) IC TXRX CAN FD 8MBPS Vio:1.8-5V Standby 8SOIC; Mfr: Texas Instruments; PN: 1620
U24 U25 = 1564-ESDCAN06-2BWY: (-55 to 175 DegC AEC) TVS DIODE CAN 2-ch 35V Vcl: 59Vmax, 8/20:3A, ESD:30KV air,30KV cont, 15pF, SOT323; Mfr: STMicroelectronics; PN: 1564
X30-X33 = 000-TestPoint: as X3-X7 on sheet 800_Peripherals

## Sheet 500_USB_Hub.SchDoc: Ivy - Verdin Industrial Board Rev 1.1
size A3; Organization: Toradex Solutions Inc.; Address1: 6415 Northwest Drive; Address2: Mississauga, ON, L4V 1X1; Address3: Canada
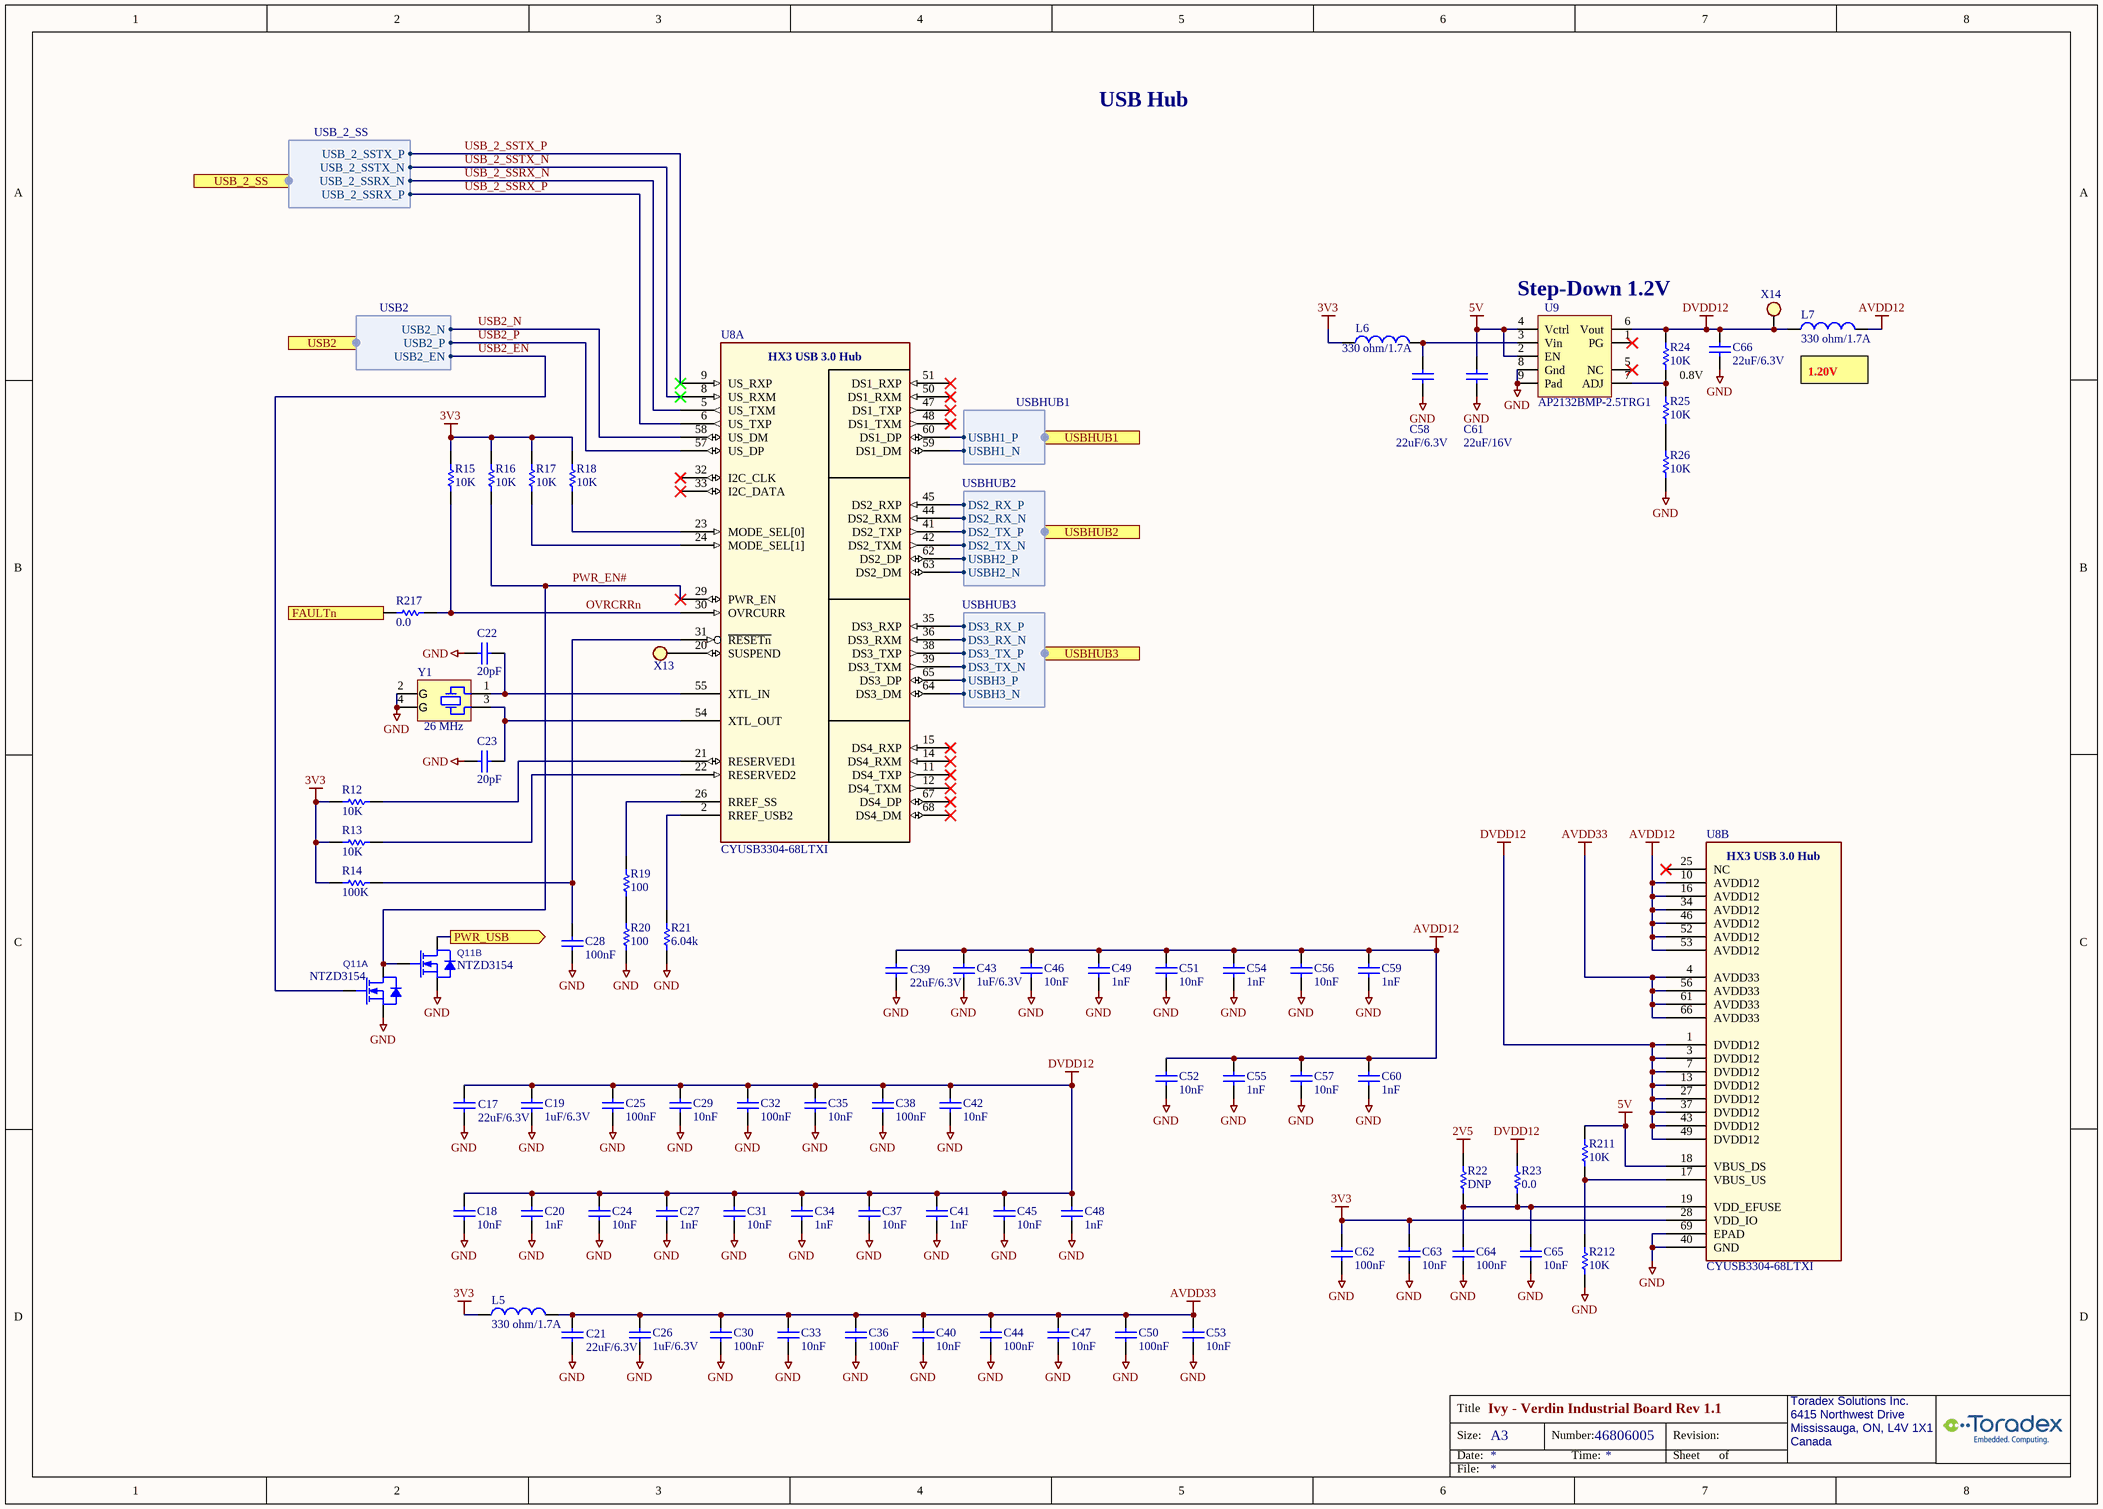
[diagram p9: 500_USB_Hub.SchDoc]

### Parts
C17  22uF/6.3V  [C0402_CAPC1005L]
C18  10nF  [C0402_CAPC1005L]
C19  value 1uF/6.3V  [C0402_CAPC1005L]  (hidden comment: 1006-Cap-0402-1uF/6V3)
C20  value 1nF  [C0402_CAPC1005L]  (hidden comment: 0318-Cap-0402-1nF/50V)
C21  22uF/6.3V  [C0402_CAPC1005L]
C22  value 20pF  [C0402_CAPC1005L]  (hidden comment: 1555-Cap-0402-20pF)
C23  value 20pF  [C0402_CAPC1005L]  (hidden comment: 1555-Cap-0402-20pF)
C24  10nF  [C0402_CAPC1005L]
C25  100nF  [C0402_CAPC1005L]
C26  value 1uF/6.3V  [C0402_CAPC1005L]  (hidden comment: 1006-Cap-0402-1uF/6V3)
C27  value 1nF  [C0402_CAPC1005L]  (hidden comment: 0318-Cap-0402-1nF/50V)
C28  100nF  [C0402_CAPC1005L]
C29  10nF  [C0402_CAPC1005L]
C30  100nF  [C0402_CAPC1005L]
C31  10nF  [C0402_CAPC1005L]
C32  100nF  [C0402_CAPC1005L]
C33  10nF  [C0402_CAPC1005L]
C34  value 1nF  [C0402_CAPC1005L]  (hidden comment: 0318-Cap-0402-1nF/50V)
C35  10nF  [C0402_CAPC1005L]
C36  100nF  [C0402_CAPC1005L]
C37  10nF  [C0402_CAPC1005L]
C38  100nF  [C0402_CAPC1005L]
C39  22uF/6.3V  [C0402_CAPC1005L]
C40  10nF  [C0402_CAPC1005L]
C41  value 1nF  [C0402_CAPC1005L]  (hidden comment: 0318-Cap-0402-1nF/50V)
C42  10nF  [C0402_CAPC1005L]
C43  value 1uF/6.3V  [C0402_CAPC1005L]  (hidden comment: 1006-Cap-0402-1uF/6V3)
C44  100nF  [C0402_CAPC1005L]
C45  10nF  [C0402_CAPC1005L]
C46  10nF  [C0402_CAPC1005L]
C47  10nF  [C0402_CAPC1005L]
C48  value 1nF  [C0402_CAPC1005L]  (hidden comment: 0318-Cap-0402-1nF/50V)
C49  value 1nF  [C0402_CAPC1005L]  (hidden comment: 0318-Cap-0402-1nF/50V)
C50  100nF  [C0402_CAPC1005L]
C51  10nF  [C0402_CAPC1005L]
C52  10nF  [C0402_CAPC1005L]
C53  10nF  [C0402_CAPC1005L]
C54  value 1nF  [C0402_CAPC1005L]  (hidden comment: 0318-Cap-0402-1nF/50V)
C55  value 1nF  [C0402_CAPC1005L]  (hidden comment: 0318-Cap-0402-1nF/50V)
C56  10nF  [C0402_CAPC1005L]
C57  10nF  [C0402_CAPC1005L]
C58  22uF/6.3V  [C0402_CAPC1005L]
C59  value 1nF  [C0402_CAPC1005L]  (hidden comment: 0318-Cap-0402-1nF/50V)
C60  value 1nF  [C0402_CAPC1005L]  (hidden comment: 0318-Cap-0402-1nF/50V)
C61  value 22uF/16V  [C/0805]  (hidden comment: 1314-Cap-0805-22uF/16V)
C62  100nF  [C0402_CAPC1005L]
C63  10nF  [C0402_CAPC1005L]
C64  100nF  [C0402_CAPC1005L]
C65  10nF  [C0402_CAPC1005L]
C66  22uF/6.3V  [C0402_CAPC1005L]
L5  value 330 ohm/1.7A  [INDC1608x095]  (hidden comment: 0405-Fer-0603-330ohm/1.7A)
L6  value 330 ohm/1.7A  [INDC1608x095]  (hidden comment: 0405-Fer-0603-330ohm/1.7A)
L7  value 330 ohm/1.7A  [INDC1608x095]  (hidden comment: 0405-Fer-0603-330ohm/1.7A)
Q11  NTZD3154  [SOT563]  (parts A,B of 2)
R12  value 10K  [R0402_RESC1005L]  (hidden comment: 1572-Res-0402-10K)
R13  value 10K  [R0402_RESC1005L]  (hidden comment: 1572-Res-0402-10K)
R14  value 100K  [R0402_RESC1005L]  (hidden comment: 1977-Res-0402-100K)
R15  value 10K  [R0402_RESC1005L]  (hidden comment: 1572-Res-0402-10K)
R16  value 10K  [R0402_RESC1005L]  (hidden comment: 1572-Res-0402-10K)
R17  value 10K  [R0402_RESC1005L]  (hidden comment: 1572-Res-0402-10K)
R18  value 10K  [R0402_RESC1005L]  (hidden comment: 1572-Res-0402-10K)
R19  value 100  [R/0603]  (hidden comment: 1973-Res-0603-100ohm)
R20  value 100  [R/0603]  (hidden comment: 1973-Res-0603-100ohm)
R21  value 6.04k  [R0402_RESC1005L]  (hidden comment: 2075-Res-0402-6.04K)
R22  value DNP  [R/0603]  (hidden comment: 0000-Res-0603-DNP)
R23  value 0.0  [R/0603]  (hidden comment: 0195-Res-0603-0.0ohm)
R24  value 10K  [R0402_RESC1005L]  (hidden comment: 1572-Res-0402-10K)
R25  value 10K  [R0402_RESC1005L]  (hidden comment: 1572-Res-0402-10K)
R26  value 10K  [R0402_RESC1005L]  (hidden comment: 1572-Res-0402-10K)
R211  value 10K  [R0402_RESC1005L]  (hidden comment: 1572-Res-0402-10K)
R212  value 10K  [R0402_RESC1005L]  (hidden comment: 1572-Res-0402-10K)
R217  value 0.0  [R/0603]  (hidden comment: 0195-Res-0603-0.0ohm)
U8  CYUSB3304-68LTXI  [QFN68_LT68B_CYP]  (parts A,B of 2)
U9  AP2132BMP-2.5TRG1  [SOP-9 TP_ALT]
X13  000-TestPoint2  [TestPoint_3]  (value not drawn)
X14  000-TestPoint2  [TestPoint_3]  (value not drawn)
Y1  value 26 MHz  [OSC_4-SMD_(2.0x1.6)]  (hidden comment: 2097-Xtal 26MHz 2.0x1.6mm)

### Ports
FAULTn (in), PWR_USB (out), USB2 (harness USB2), USB_2_SS (harness USB_2_SS), USBHUB1 (harness USBHUB1), USBHUB2 (harness USBHUB2), USBHUB3 (harness USBHUB3)

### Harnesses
USB2: USB2_N, USB2_P, USB2_EN
USBHUB1: USBH1_N, USBH1_P
USBHUB2: USBH2_N, USBH2_P, DS2_TX_N, DS2_TX_P, DS2_RX_N, DS2_RX_P
USBHUB3: USBH3_N, USBH3_P, DS3_TX_N, DS3_TX_P, DS3_RX_N, DS3_RX_P
USB_2_SS: USB_2_SSTX_N, USB_2_SSTX_P, USB_2_SSRX_N, USB_2_SSRX_P

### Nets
2V5: R22.2
3V3: C62.2 C63.2 L5.1 L6.1 R12.1 R13.1 R14.2 R15.2 R16.2 R17.1 R18.1 U8.28(VDD_IO)
5V: C61.2 R211.2 U8.18(VBUS_DS) U9.2(EN) U9.4(Vctrl)
AVDD12: C39.2 C43.2 C46.2 C49.1 C51.2 C52.2 C54.1 C55.1 C56.2 C57.2 C59.1 C60.1 L7.2 U8.10(AVDD12) U8.16(AVDD12) U8.34(AVDD12) U8.46(AVDD12) U8.52(AVDD12) U8.53(AVDD12)
AVDD33: C21.2 C26.2 C30.2 C33.2 C36.2 C40.2 C44.2 C47.2 C50.2 C53.2 L5.2 U8.4(AVDD33) U8.56(AVDD33) U8.61(AVDD33) U8.66(AVDD33)
DVDD12: C17.2 C18.2 C19.2 C20.1 C24.2 C25.2 C27.1 C29.2 C31.2 C32.2 C34.1 C35.2 C37.2 C38.2 C41.1 C42.2 C45.2 C48.1 C66.2 L7.1 R23.1 R24.2 U8.1(DVDD12) U8.3(DVDD12) U8.7(DVDD12) U8.13(DVDD12) U8.27(DVDD12) U8.37(DVDD12) U8.43(DVDD12) U8.49(DVDD12) U9.6(Vout) X14.1
GND: C17.1 C18.1 C19.1 C20.2 C21.1 C22.1 C23.1 C24.1 C25.1 C26.1 C27.2 C28.1 C29.1 C30.1 C31.1 C32.1 C33.1 C34.2 C35.1 C36.1 C37.1 C38.1 C39.1 C40.1 C41.2 C42.1 C43.1 C44.1 C45.1 C46.1 C47.1 C48.2 C49.2 C50.1 C51.1 C52.1 C53.1 C54.2 C55.2 C56.1 C57.1 C58.1 C59.2 C60.2 C61.1 C62.1 C63.1 C64.1 C65.1 C66.1 Q11.1(S) Q11.4(S) R20.2 R21.2 R26.1 R212.1 U8.40(GND) U8.69(EPAD) U9.8(Gnd) U9.9(Pad) Y1.2(GND) Y1.4(GND)
DS2_RX_N: U8.44(DS2_RXM) ; port USBHUB2.DS2_RX_N
DS2_RX_P: U8.45(DS2_RXP) ; port USBHUB2.DS2_RX_P
DS2_TX_N: U8.42(DS2_TXM) ; port USBHUB2.DS2_TX_N
DS2_TX_P: U8.41(DS2_TXP) ; port USBHUB2.DS2_TX_P
DS3_RX_N: U8.36(DS3_RXM) ; port USBHUB3.DS3_RX_N
DS3_RX_P: U8.35(DS3_RXP) ; port USBHUB3.DS3_RX_P
DS3_TX_N: U8.39(DS3_TXM) ; port USBHUB3.DS3_TX_N
DS3_TX_P: U8.38(DS3_TXP) ; port USBHUB3.DS3_TX_P
FAULTn: R217.1 ; port FAULTn
OVRCRRn: R15.1 R217.2 U8.30(OVRCURR)
PWR_EN#: Q11.5(G) Q11.6(D) R16.1 U8.29(PWR_EN)
PWR_USB: Q11.3(D) ; port PWR_USB
USB2_EN: Q11.2(G) ; port USB2.USB2_EN
USB2_N: U8.58(US_DM) ; port USB2.USB2_N
USB2_P: U8.57(US_DP) ; port USB2.USB2_P
USB_2_SSRX_N: U8.5(US_TXM) ; port USB_2_SS.USB_2_SSRX_N
USB_2_SSRX_P: U8.6(US_TXP) ; port USB_2_SS.USB_2_SSRX_P
USB_2_SSTX_N: U8.8(US_RXM) ; port USB_2_SS.USB_2_SSTX_N
USB_2_SSTX_P: U8.9(US_RXP) ; port USB_2_SS.USB_2_SSTX_P
USBH2_N: U8.63(DS2_DM) ; port USBHUB2.USBH2_N
USBH2_P: U8.62(DS2_DP) ; port USBHUB2.USBH2_P
USBH3_N: U8.64(DS3_DM) ; port USBHUB3.USBH3_N
USBH3_P: U8.65(DS3_DP) ; port USBHUB3.USBH3_P
NetC22_2: C22.2 U8.55(XTL_IN) Y1.1
NetC23_2: C23.2 U8.54(XTL_OUT) Y1.3
NetC28_2: C28.2 R14.1 U8.31(~{RESETn})
NetC58_2: C58.2 L6.2 U9.3(Vin)
NetC64_2: C64.2 C65.2 R22.1 R23.2 U8.19(VDD_EFUSE)
NetJ8_36: U8.59(DS1_DM) ; port USBHUB1.USBH1_N
NetJ8_38: U8.60(DS1_DP) ; port USBHUB1.USBH1_P
NetR12_2: R12.2 U8.21(RESERVED1)
NetR13_2: R13.2 U8.22(RESERVED2)
NetR17_2: R17.2 U8.24(MODE_SEL[1])
NetR18_2: R18.2 U8.23(MODE_SEL[0])
NetR19_1: R19.1 U8.26(RREF_SS)
NetR19_2: R19.2 R20.1
NetR21_1: R21.1 U8.2(RREF_USB2)
NetR24_1: R24.1 R25.2 U9.7(ADJ)
NetR25_1: R25.1 R26.2
NetR211_1: R211.1 R212.2 U8.17(VBUS_US)
NetU8_20: U8.20(SUSPEND) X13.1

Not connected (* = marked no-connect by the designer): U8 11(DS4_TXP)* 12(DS4_TXM)* 14(DS4_RXM)* 15(DS4_RXP)* 25(NC)* 32(I2C_CLK)* 33(I2C_DATA)* 47(DS1_TXP)* 48(DS1_TXM)* 50(DS1_RXM)* 51(DS1_RXP)* 67(DS4_DP)* 68(DS4_DM)*; U9 1(PG)* 5(NC)*

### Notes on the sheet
- USB Hub
- Step-Down 1.2V
- 0.8V
- (near L7) 1.20V

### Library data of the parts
C17 C21 C39 = 2404-Cap-0402-22uF/6.3V: (-55 to 85 DegC) CAP CER 22UF 6.3V 20% X5R 0402; Mfr: Murata; MfrNo: GRM155R60J226ME11D; PN: 2404
C18 C24 C29 C31 C33 C35 C37 C40 C42 C45-C47 C51-C53 C56 C57 C63 C65 = 1149-Cap-0402-10nF/50V: Cap Ceramic 10nF 50V X7R 10% 0402; Mfr: Yageo; MfrNo: CC0402KRX7R9BB103; Alt: CL05B103KB5NNNC,UMK105BJ103KV-F,CL05B103KB5NFNC,0402B103K500CT,CC0402KRX7R9BB103; PN: 1149
C19 C26 C43 = 1006-Cap-0402-1uF/6V3: Cap Ceramic 1uF 6.3V X5R 20% SMD 0402 85C T/R; Mfr: Samsung; MfrNo: CL05A105MQ5NNNC; Alt: CL05A105MP5NNNC,CL05A105KQ5NNNC,CL05A105KP5NNNC,CL05A105JQ5NNNC; PN: 1006; Desc: Cap Ceramic 1uF 6.3V X5R 20% SMD 0402 85C Paper T/R
C20 C27 C34 C41 C48 C49 C54 C55 C59 C60 = 0318-Cap-0402-1nF/50V: CAP CER 1000PF 50V 5% NP0 0402; Mfr: Samsung Electro-Mechanics America, Inc; MfrNo: CL05C102JB5NNNC; Alt: 399-10034-1-ND; PN: 318; Alt2: 490-3244-1-ND
C22 C23 = 1555-Cap-0402-20pF: (-55 to 125 DegC AEC) CAP CER 20PF 5% 50V C0G/NPO 0402; MfrNo: CL05C200JB51PNC; Mfr: Samsung; PN: 1555; Alt: GCM1555C1H200JA16D,GCM1555C1H200GA16D
C25 C30 C32 C36 C38 C44 C50 = 1566-Cap-0402-100nF/50V: (-55 to 125 DegC AEC) Cap Ceramic 0.1uF 50V X7R 10% 0402; Mfr: Murata; MfrNo: GRT155R71H104KE01D; Alt: CL05B104KB54PNC,GCM155R71H104ME02D,GCM155R71H104KE02D,GCM155R71H104KE02J; PN: 1566
C28 = 1566-Cap-0402-100nF/50V: as C9-C11 on sheet 800_Peripherals
C58 C66 = 2404-Cap-0402-22uF/6.3V: as C12 on sheet 800_Peripherals
C61 = 1314-Cap-0805-22uF/16V: as C115 on sheet 300_CAN_Transceivers
C62 C64 = 1566-Cap-0402-100nF/50V: as C127 on sheet 300_CAN_Transceivers
L5-L7 = 0405-Fer-0603-330ohm/1.7A: as L4 on sheet 800_Peripherals
Q11 = 1146-NTZD3154NT1G: (-55 to 150 DegC) MOSFET 2N-CH (dual) 20V 0.54A SOT-563 1.6x1.6mm Vth:1V Ron typ:400m@4.5V, 500m@2.5V, 700m@1.8V; Mfr: ON Semiconductor; PN: 1146; Alt: NTZD3154NT5G,PMDT290UNE,115
R12 R13 R15-R18 R211 R212 = 1572-Res-0402-10K: as R149 on sheet 900_LTE
R14 = 1977-Res-0402-100K: as R86 on sheet 300_CAN_Transceivers
R19 R20 = 1973-Res-0603-100ohm: (-55 to 155 DegC) RES 100 OHM 1/10W 1% 0603; Mfr: Yageo; MfrNo: RC0603FR-07100RL; PN: 1973
R21 = 2075-Res-0402-6.04K: (-55 to 155 DegC) RES 6.04K OHM 1/10W 1% 0402 SMD; Mfr: Panasonic; MfrNo: ERJ-2RKF6041X; PN: 2075
R22 = 0000-Res-0603-DNP: RES 0603
R23 = 0195-Res-0603-0.0ohm: RES 0.0 OHM 1/10W JUMP 0603; Mfr: Samsung; MfrNo: RC1608J000CS; Alt: 311-0.0GRCT-ND; PN: 195; Alt2: A106051CT-ND; TR: 1276-3510-2-ND
R24-R26 = 1572-Res-0402-10K: (-55 to 155 DegC AEC) RES 10K OHM 1% 1/16W 100ppm 0402; MfrNo: RMCF0402FT10K0; Mfr: Stackpole Electronics; Alt: AC0402FR-0710KL,AC0402FR-1310KL,CRGCQ0402F10K; PN: 1572
R217 = 0195-Res-0603-0.0ohm: as R218 on sheet 800_Peripherals
U8 = 2096-CYUSB3304-68LTXI: (-40 to 85 DegC) IC USB 3.0 HUB 4-PORT 68QFN; Mfr: Infineon Technologies; PN: 2096
U9 = 1467-AP2132BMP-2.5: (-40 to 85 DegC) IC REG LDO LINEAR POS ADJ 5V 2A 8SO; Mfr: Diodes; PN: 1467; Desc: (-40 to 85 DegC) IC REG BUCK ADJ Sync 5A Vin:3.8 to 40V 100-2200kHz FSS (spread spectrum) MaxDuty:100% SO-8EP; Note: These can be also used with adjust Voltage circuit: AP2132BMP-1.2TRG1, AP2132BMP-1.5TRG1
X13 X14 = 000-TestPoint2: as X8 on sheet 800_Peripherals
Y1 = 2097-Xtal 26MHz 2.0x1.6mm: (-40 to 85 DegC) XTAL CRYSTAL 26.0000MHZ 12PF SMD +-15ppm +-10ppm 2.0x1.6mm; MfrNo: XRCGB26M000F1SADR0; Mfr: Murata Electronics; PN: 2097; Desc: (-20 to 70 DegC) XTAL CRYSTAL 26.0000MHZ 12PF SMD +-10ppm +-10ppm 3.2x2.5mm

## Sheet 700_Relays.SchDoc: Ivy - Verdin Industrial Board Rev 1.1
size Letter; Organization: Toradex Solutions Inc.; Address1: 6415 Northwest Drive; Address2: Mississauga, ON, L4V 1X1; Address3: Canada
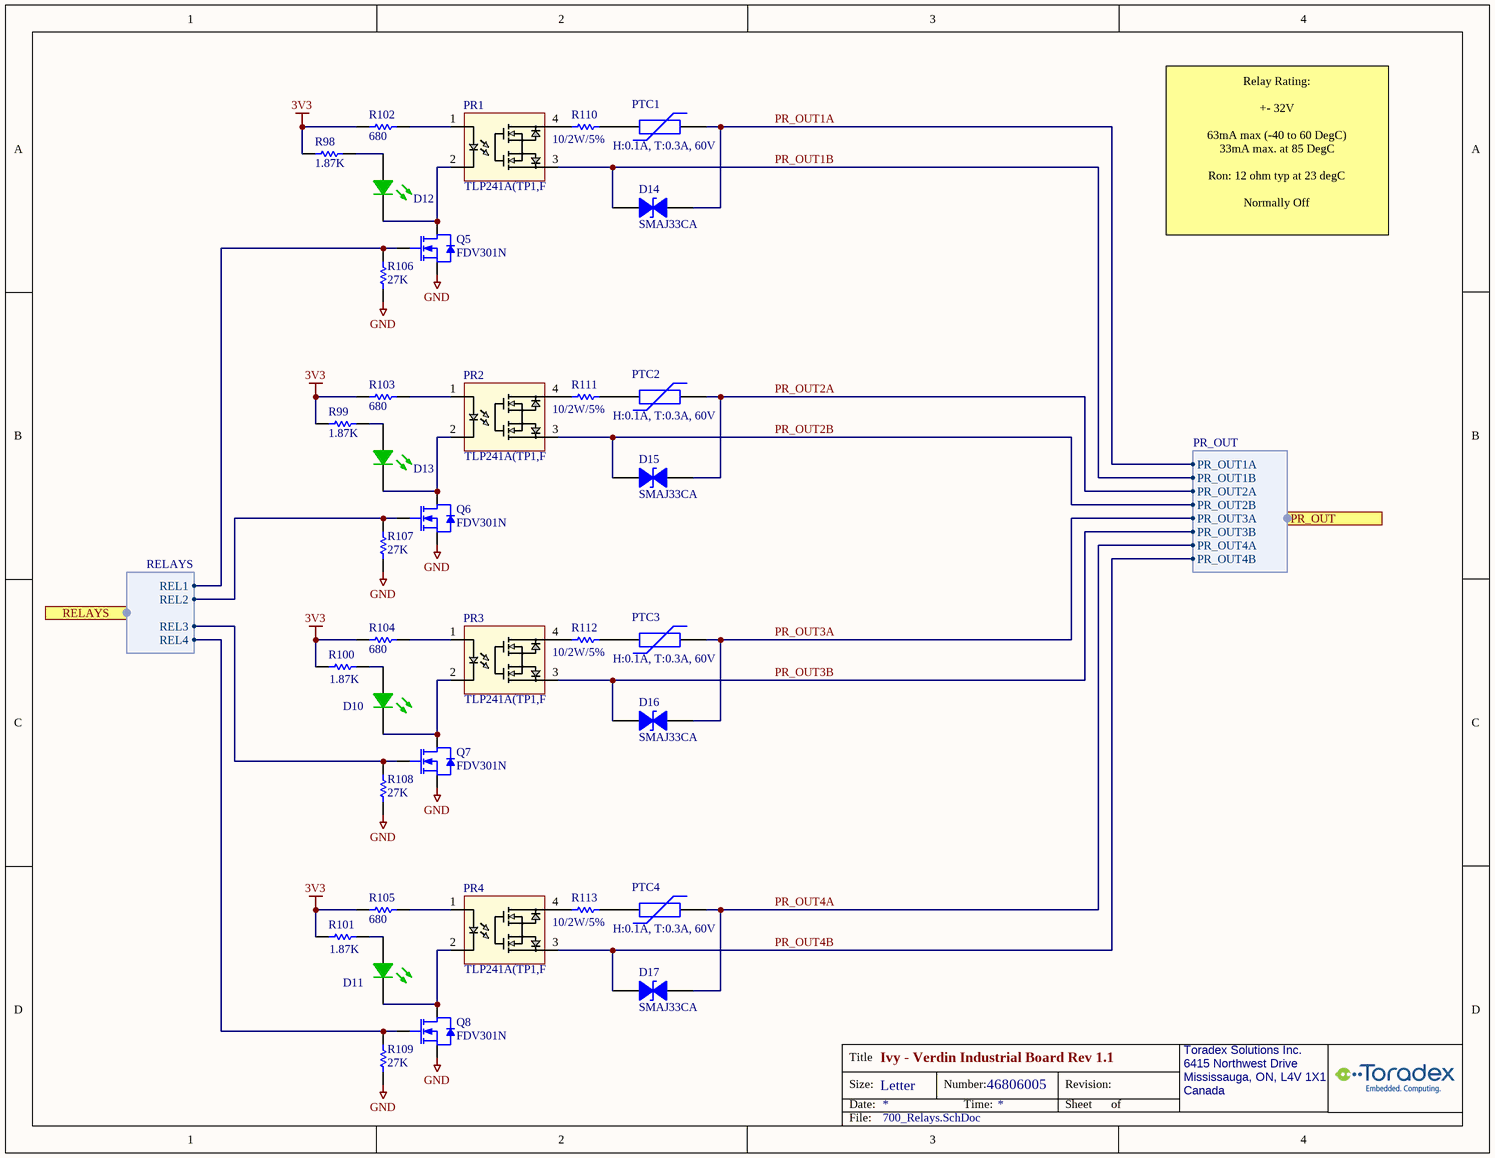
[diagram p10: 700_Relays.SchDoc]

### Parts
D10  Status  [LED-SMT-0603_APT1608CGCK]  (value not drawn)
D11  Status  [LED-SMT-0603_APT1608CGCK]  (value not drawn)
D12  Status  [LED-SMT-0603_APT1608CGCK]  (value not drawn)
D13  Status  [LED-SMT-0603_APT1608CGCK]  (value not drawn)
D14  SMAJ33CA  [SMAJ_TRANSIL]
D15  SMAJ33CA  [SMAJ_TRANSIL]
D16  SMAJ33CA  [SMAJ_TRANSIL]
D17  SMAJ33CA  [SMAJ_TRANSIL]
PR1  TLP241A  [TLP241A_TP1]  (value not drawn)
PR2  TLP241A  [TLP241A_TP1]  (value not drawn)
PR3  TLP241A  [TLP241A_TP1]  (value not drawn)
PR4  TLP241A  [TLP241A_TP1]  (value not drawn)
PTC1  H:0.1A, T:0.3A, 60V  [PTC_1812]
PTC2  H:0.1A, T:0.3A, 60V  [PTC_1812]
PTC3  H:0.1A, T:0.3A, 60V  [PTC_1812]
PTC4  H:0.1A, T:0.3A, 60V  [PTC_1812]
Q5  FDV301N  [SOT23]
Q6  FDV301N  [SOT23]
Q7  FDV301N  [SOT23]
Q8  FDV301N  [SOT23]
R98  value 1.87K  [R0402_RESC1005L]  (hidden comment: 1536-Res-0402-1.87K)
R99  value 1.87K  [R0402_RESC1005L]  (hidden comment: 1536-Res-0402-1.87K)
R100  value 1.87K  [R0402_RESC1005L]  (hidden comment: 1536-Res-0402-1.87K)
R101  value 1.87K  [R0402_RESC1005L]  (hidden comment: 1536-Res-0402-1.87K)
R102  value 680  [R/0603]  (hidden comment: 0864-Res-0603-680ohm)
R103  value 680  [R/0603]  (hidden comment: 0864-Res-0603-680ohm)
R104  value 680  [R/0603]  (hidden comment: 0864-Res-0603-680ohm)
R105  value 680  [R/0603]  (hidden comment: 0864-Res-0603-680ohm)
R106  value 27K  [R0402_RESC1005L]  (hidden comment: 1538-Res-0402-27k)
R107  value 27K  [R0402_RESC1005L]  (hidden comment: 1538-Res-0402-27k)
R108  value 27K  [R0402_RESC1005L]  (hidden comment: 1538-Res-0402-27k)
R109  value 27K  [R0402_RESC1005L]  (hidden comment: 1538-Res-0402-27k)
R110  value 10/2W/5%  [R/2512]  (hidden comment: 1424-Res-2512-10ohm-5%-2W)
R111  value 10/2W/5%  [R/2512]  (hidden comment: 1424-Res-2512-10ohm-5%-2W)
R112  value 10/2W/5%  [R/2512]  (hidden comment: 1424-Res-2512-10ohm-5%-2W)
R113  value 10/2W/5%  [R/2512]  (hidden comment: 1424-Res-2512-10ohm-5%-2W)

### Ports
PR_OUT (harness PR_OUT), RELAYS (harness RELAYS)

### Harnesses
RELAYS: REL1, REL2, REL3, REL4
PR_OUT: PR_OUT1A, PR_OUT1B, PR_OUT2A, PR_OUT2B, PR_OUT3A, PR_OUT3B, PR_OUT4A, PR_OUT4B

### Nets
3V3: R98.1 R99.1 R100.1 R101.1 R102.1 R103.1 R104.1 R105.1
GND: Q5.2(S) Q6.2(S) Q7.2(S) Q8.2(S) R106.1 R107.1 R108.1 R109.1
PR_OUT1A: D14.2 PTC1.2 ; port PR_OUT.PR_OUT1A
PR_OUT1B: D14.1 PR1.3 ; port PR_OUT.PR_OUT1B
PR_OUT2A: D15.2 PTC2.2 ; port PR_OUT.PR_OUT2A
PR_OUT2B: D15.1 PR2.3 ; port PR_OUT.PR_OUT2B
PR_OUT3A: D16.2 PTC3.2 ; port PR_OUT.PR_OUT3A
PR_OUT3B: D16.1 PR3.3 ; port PR_OUT.PR_OUT3B
PR_OUT4A: D17.2 PTC4.2 ; port PR_OUT.PR_OUT4A
PR_OUT4B: D17.1 PR4.3 ; port PR_OUT.PR_OUT4B
REL1: Q5.1(G) R106.2 ; port RELAYS.REL1
REL2: Q6.1(G) R107.2 ; port RELAYS.REL2
REL3: Q7.1(G) R108.2 ; port RELAYS.REL3
REL4: Q8.1(G) R109.2 ; port RELAYS.REL4
NetD10_1: D10.1(A) R100.2
NetD10_2: D10.2(K) PR3.2 Q7.3(D)
NetD11_1: D11.1(A) R101.2
NetD11_2: D11.2(K) PR4.2 Q8.3(D)
NetD12_1: D12.1(A) R98.2
NetD12_2: D12.2(K) PR1.2 Q5.3(D)
NetD13_1: D13.1(A) R99.2
NetD13_2: D13.2(K) PR2.2 Q6.3(D)
NetPR1_1: PR1.1 R102.2
NetPR1_4: PR1.4 R110.2
NetPR2_1: PR2.1 R103.2
NetPR2_4: PR2.4 R111.2
NetPR3_1: PR3.1 R104.2
NetPR3_4: PR3.4 R112.2
NetPR4_1: PR4.1 R105.2
NetPR4_4: PR4.4 R113.2
NetPTC1_1: PTC1.1 R110.1
NetPTC2_1: PTC2.1 R111.1
NetPTC3_1: PTC3.1 R112.1
NetPTC4_1: PTC4.1 R113.1

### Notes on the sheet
- Relay Rating:
  +- 32V
  63mA max (-40 to 60 DegC)
  33mA max. at 85 DegC
  Ron: 12 ohm typ at 23 degC
  Normally Off

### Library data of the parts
D10-D13 = 0333-LED Green 0603: as D18 on sheet 900_LTE
D14-D17 = 0581-SMAJ33CA: (-55 to 150 DegC) TVS DIODE 33VWM Vbrm:36.7V Vcl:53.3V 400W SMA; MfrNo: SMAJ33CA-E3/5A; Mfr: Vishay Semiconductor Diodes Division; PN: 581; Desc: (-55 to 150 DegC) TVS DIODE 33VWM Vbrm:36.7V Vstd:53.3VC SMA; Alt: SMAJ33CA-E3/61GICT-ND; Alt2: SMAJ33CABCT-ND; DR: SMAJ33CA-E3/5AGIDKR-ND; DR2: 625-SMAJ33CA-E3/5A
PR1-PR4 = 1078-PhotoRelay-TLP241A: (-40 to 85 DegC) SSR RELAY SPST-NO 2A 0-40V 90mOhm typ 5x12.5mm; Mfr: Toshiba; MfrNo: TLP241A(TP1,F; PN: 1078
PTC1-PTC4 = 1423-PTC-0.1A-60V-1812: (-40 to 85 DegC) PTC Ih:0.1A, It:0.3A, 60V, 1812, 1.6-15ohm; MfrNo: 0ZCG0010FF2C; Mfr: Bel; PN: 1423; Alt: MPTS1812L010R,MPTS1812L010,1812L010/60DR,PTSA181260V010,MF-MSMF010-2,PFMF.010.2,MINISMDC010F-2,MINIASMDC010F-2
Q5-Q8 = 0761-FDV301N: (-55 to 155 DegC) MOSFET N-CH 25V 220MA SOT-23 Vth:1.1V Ron typ:4ohm@3V Vgsm:8V; Mfr: Fairchild/ON Semiconductor; PN: 761; DR: FDV301NDKR-ND; TR: FDV301NTR-ND; Alt: DMN62D0U-13, DMN62D0U-7, DMN61D9U-7
R98-R101 = 1536-Res-0402-1.87K: as R11 on sheet 800_Peripherals
R102-R105 = 0864-Res-0603-680ohm: RES SMD 680 OHM 1% 1/10W 0603; Mfr: Yageo; MfrNo: RC0603FR-07680RL; Alt: RMCF0603FT680R; PN: 864; Alt2: AC0603FR-07680RL
R106-R109 = 1538-Res-0402-27k: as R133 on sheet 900_LTE
R110-R113 = 1424-Res-2512-10ohm-5%-2W: (-55 to 155 DegC) RES SMD 10 OHM 5% 2W Pulse 2512; MfrNo: CRM2512AJW-100ELF; Mfr: Bourns; PN: 1424; Alt: CRS2512-JX-100ELF,CRM2512AFX-10R0ELF,SR2512JK-7W10RL,SR2512FK-7W10RL

## Sheet 150_Status_LEDs.SchDoc: Ivy - Verdin Industrial Board Rev 1.1
size Letter; Organization: Toradex Solutions Inc.; Address1: 6415 Northwest Drive; Address2: Mississauga, ON, L4V 1X1; Address3: Canada
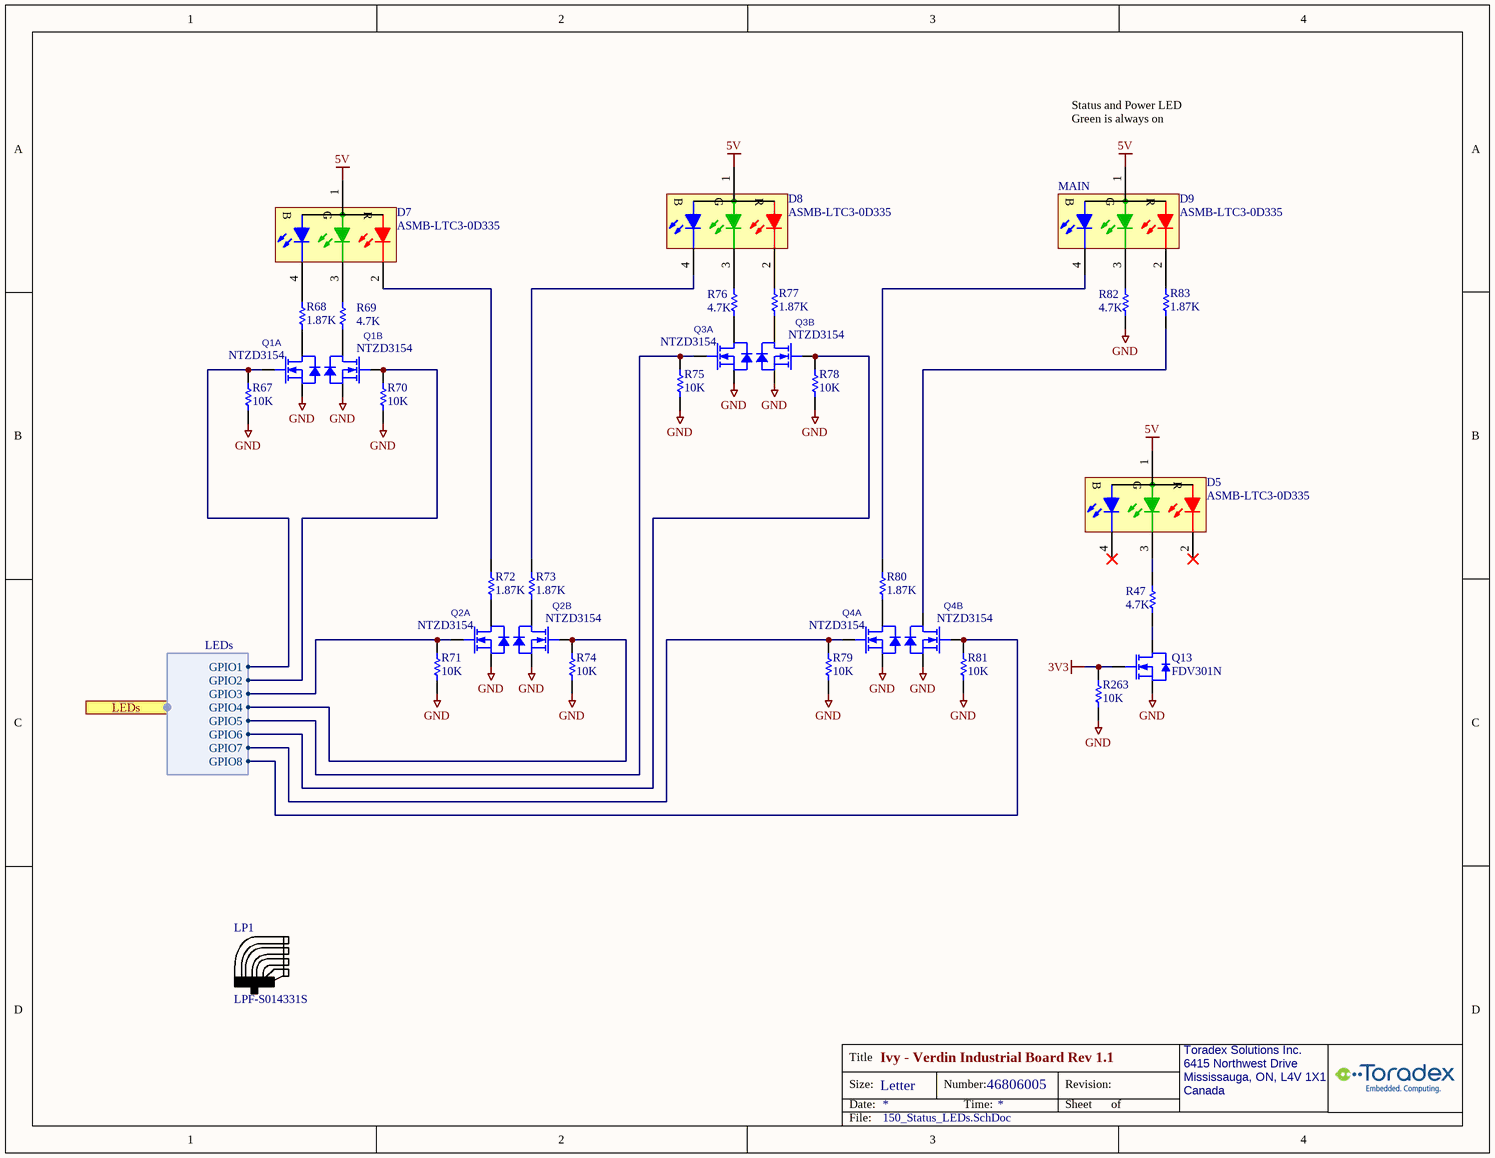
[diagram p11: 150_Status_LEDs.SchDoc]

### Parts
D5  ASMB-LTC3-0D335  [4-PLCC_LED_2121_BROADCOM]
D7  ASMB-LTC3-0D335  [4-PLCC_LED_2121_BROADCOM]
D8  ASMB-LTC3-0D335  [4-PLCC_LED_2121_BROADCOM]
D9  ASMB-LTC3-0D335  [4-PLCC_LED_2121_BROADCOM]
LP1  LPF-S014331S  [LPF-S014331S]
Q1  NTZD3154  [SOT563]  (parts A,B of 2)
Q2  NTZD3154  [SOT563]  (parts A,B of 2)
Q3  NTZD3154  [SOT563]  (parts A,B of 2)
Q4  NTZD3154  [SOT563]  (parts A,B of 2)
Q13  FDV301N  [SOT23]
R47  value 4.7K  [R0402_RESC1005L]  (hidden comment: 2233-Res-0402-4.7K)
R67  value 10K  [R0402_RESC1005L]  (hidden comment: 1572-Res-0402-10K)
R68  value 1.87K  [R0402_RESC1005L]  (hidden comment: 1536-Res-0402-1.87K)
R69  value 4.7K  [R0402_RESC1005L]  (hidden comment: 2233-Res-0402-4.7K)
R70  value 10K  [R0402_RESC1005L]  (hidden comment: 1572-Res-0402-10K)
R71  value 10K  [R0402_RESC1005L]  (hidden comment: 1572-Res-0402-10K)
R72  value 1.87K  [R0402_RESC1005L]  (hidden comment: 1536-Res-0402-1.87K)
R73  value 1.87K  [R0402_RESC1005L]  (hidden comment: 1536-Res-0402-1.87K)
R74  value 10K  [R0402_RESC1005L]  (hidden comment: 1572-Res-0402-10K)
R75  value 10K  [R0402_RESC1005L]  (hidden comment: 1572-Res-0402-10K)
R76  value 4.7K  [R0402_RESC1005L]  (hidden comment: 2233-Res-0402-4.7K)
R77  value 1.87K  [R0402_RESC1005L]  (hidden comment: 1536-Res-0402-1.87K)
R78  value 10K  [R0402_RESC1005L]  (hidden comment: 1572-Res-0402-10K)
R79  value 10K  [R0402_RESC1005L]  (hidden comment: 1572-Res-0402-10K)
R80  value 1.87K  [R0402_RESC1005L]  (hidden comment: 1536-Res-0402-1.87K)
R81  value 10K  [R0402_RESC1005L]  (hidden comment: 1572-Res-0402-10K)
R82  value 4.7K  [R0402_RESC1005L]  (hidden comment: 2233-Res-0402-4.7K)
R83  value 1.87K  [R0402_RESC1005L]  (hidden comment: 1536-Res-0402-1.87K)
R263  value 10K  [R0402_RESC1005L]  (hidden comment: 1572-Res-0402-10K)

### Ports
LEDs (harness LEDs)

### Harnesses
LEDs: GPIO1, GPIO2, GPIO3, GPIO4, GPIO5, GPIO7, GPIO8, GPIO6

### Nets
3V3: Q13.1(G) R263.2
5V: D5.1(A1) D7.1(A1) D8.1(A1) D9.1(A1)
GND: Q1.1(S) Q1.4(S) Q2.1(S) Q2.4(S) Q3.1(S) Q3.4(S) Q4.1(S) Q4.4(S) Q13.2(S) R67.1 R70.1 R71.1 R74.1 R75.1 R78.1 R79.1 R81.1 R82.1 R263.1
NetD5_3: D5.3(K2) R47.2
NetD7_2: D7.2(K3) R72.2
NetD7_3: D7.3(K2) R69.2
NetD7_4: D7.4(K1) R68.2
NetD8_2: D8.2(K3) R77.2
NetD8_3: D8.3(K2) R76.2
NetD8_4: D8.4(K1) R73.2
NetD9_2: D9.2(K3) R83.2
NetD9_3: D9.3(K2) R82.2
NetD9_4: D9.4(K1) R80.2
NetM1_30: Q1.2(G) R67.2 ; port LEDs.GPIO1
NetM1_32: Q1.5(G) R70.2 ; port LEDs.GPIO2
NetM1_34: Q2.2(G) R71.2 ; port LEDs.GPIO3
NetM1_36: Q2.5(G) R74.2 ; port LEDs.GPIO4
NetM1_44: Q3.5(G) R78.2 ; port LEDs.GPIO6
NetM1_46: Q4.2(G) R79.2 ; port LEDs.GPIO7
NetM1_48: Q4.5(G) R81.2 ; port LEDs.GPIO8
NetM1_54: Q3.2(G) R75.2 ; port LEDs.GPIO5
NetQ1_3: Q1.3(D) R69.1
NetQ1_6: Q1.6(D) R68.1
NetQ2_3: Q2.3(D) R73.1
NetQ2_6: Q2.6(D) R72.1
NetQ3_3: Q3.3(D) R77.1
NetQ3_6: Q3.6(D) R76.1
NetQ4_3: Q4.3(D) R83.1
NetQ4_6: Q4.6(D) R80.1
NetQ13_3: Q13.3(D) R47.1

Not connected (* = marked no-connect by the designer): D5 2(K3)* 4(K1)*

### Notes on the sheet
- Status and Power LED
- Green is always on
- (near D9) MAIN

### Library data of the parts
D5 D7-D9 = 2349-LED RGB 4SMD: (-40 to 85 DegC) LED RGB 2.1mm x 1.9mm x 1mm 4SMD vf=2V Red, 2.6V Green, 2.7V Blue; Mfr: Broadcom; PN: 2349
LP1 = 2302-Lightpipe Lumex LPF-S014331S: Lightpipe R/A for 1210 size LEDs. 3.2mm x 1.8mm lens size. Board mount, press fit.; Mfr: Lumex; PN: 2302
Q1-Q4 = 1146-NTZD3154NT1G: as Q11 on sheet 500_USB_Hub
Q13 = 0761-FDV301N: as Q5 on sheet 700_Relays
R47 R69 R76 R82 = 2233-Res-0402-4.7K: as R136 on sheet 900_LTE
R67 R70 R71 R74 R75 R78 R79 R81 R263 = 1572-Res-0402-10K: as R149 on sheet 900_LTE
R68 R72 R73 R77 R80 R83 = 1536-Res-0402-1.87K: as R11 on sheet 800_Peripherals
